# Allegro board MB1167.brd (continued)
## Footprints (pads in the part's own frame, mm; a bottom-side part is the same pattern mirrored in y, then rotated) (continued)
CLM-120-02-L-D
  rect 0.61x1.499 smd: 1(-9.5,-1.57) 2(-9.5,1.57) 3(-8.5,-1.57) 4(-8.5,1.57) 5(-7.5,-1.57) 6(-7.5,1.57) 7(-6.5,-1.57) 8(-6.5,1.57) 9(-5.5,-1.57) 10(-5.5,1.57) 11(-4.5,-1.57) 12(-4.5,1.57) 13(-3.5,-1.57) 14(-3.5,1.57) 15(-2.5,-1.57) 16(-2.5,1.57) 17(-1.5,-1.57) 18(-1.5,1.57) 19(-0.5,-1.57) 20(-0.5,1.57) 21(0.5,-1.57) 22(0.5,1.57) 23(1.5,-1.57) 24(1.5,1.57) 25(2.5,-1.57) 26(2.5,1.57) 27(3.5,-1.57) 28(3.5,1.57) 29(4.5,-1.57) 30(4.5,1.57) 31(5.5,-1.57) 32(5.5,1.57) 33(6.5,-1.57) 34(6.5,1.57) 35(7.5,-1.57) 36(7.5,1.57) 37(8.5,-1.57) 38(8.5,1.57) 39(9.5,-1.57) 40(9.5,1.57)
  round 4.699 hole 3.2: 41(-15.249,0) 42(15.25,0)
CONN_DLR11H0
  round 1.956 hole 1.956 unplated: (-7.14,2.3) (-2.54,-3.7) (2.06,2.3)
  rect 1.219x1.219 hole 0.813: 1(0,0)
  round 1.219 hole 0.813: 2(-2.54,0) 3(-5.08,0)
COUPON
  rect 1.422x1.422 hole 1.016: 1(-3.444,-2.54)
  round 1.422 hole 1.016: 2(-3.444,0) 3(-3.444,2.54) 4(3.447,-2.54) 5(3.447,0) 6(3.447,2.54)
DB9_M
  rect 1.778x2.032 hole 0.965: 1(5.537,0)
  oval 1.778x2.032 hole 0.965: 2(2.769,0) 3(0,0) 4(-2.769,0) 5(-5.537,0) 6(4.166,2.794) 7(1.397,2.794) 8(-1.372,2.794) 9(-4.14,2.794)
  oval 4.572x2.286 hole 3.556x1.27: 10(-12.522,1.397) 11(12.522,1.397)
FBGA64_1_11X13
  round 0.457 smd: A1(-3.5,3.5) A2(-2.5,3.5) A3(-1.5,3.5) A4(-0.5,3.5) A5(0.5,3.5) A6(1.5,3.5) A7(2.5,3.5) A8(3.5,3.5) B1(-3.5,2.5) B2(-2.5,2.5) B3(-1.5,2.5) B4(-0.5,2.5) B5(0.5,2.5) B6(1.5,2.5) B7(2.5,2.5) B8(3.5,2.5) C1(-3.5,1.5) C2(-2.5,1.5) C3(-1.5,1.5) C4(-0.5,1.5) C5(0.5,1.5) C6(1.5,1.5) C7(2.5,1.5) C8(3.5,1.5) D1(-3.5,0.5) D2(-2.5,0.5) D3(-1.5,0.5) D4(-0.5,0.5) D5(0.5,0.5) D6(1.5,0.5) D7(2.5,0.5) D8(3.5,0.5) E1(-3.5,-0.5) E2(-2.5,-0.5) E3(-1.5,-0.5) E4(-0.5,-0.5) E5(0.5,-0.5) E6(1.5,-0.5) E7(2.5,-0.5) E8(3.5,-0.5) F1(-3.5,-1.5) F2(-2.5,-1.5) F3(-1.5,-1.5) F4(-0.5,-1.5) F5(0.5,-1.5) F6(1.5,-1.5) F7(2.5,-1.5) F8(3.5,-1.5) G1(-3.5,-2.5) G2(-2.5,-2.5) G3(-1.5,-2.5) G4(-0.5,-2.5) G5(0.5,-2.5) G6(1.5,-2.5) G7(2.5,-2.5) G8(3.5,-2.5) H1(-3.5,-3.5) H2(-2.5,-3.5) H3(-1.5,-3.5) H4(-0.5,-3.5) H5(0.5,-3.5) H6(1.5,-3.5) H7(2.5,-3.5) H8(3.5,-3.5)
FBGA90_0R8_8X13
  round 0.406 smd: A1(-3.2,5.6) A2(-2.4,5.6) A3(-1.6,5.6) A7(1.6,5.6) A8(2.4,5.6) A9(3.2,5.6) B1(-3.2,4.8) B2(-2.4,4.8) B3(-1.6,4.8) B7(1.6,4.8) B8(2.4,4.8) B9(3.2,4.8) C1(-3.2,4) C2(-2.4,4) C3(-1.6,4) C7(1.6,4) C8(2.4,4) C9(3.2,4) D1(-3.2,3.2) D2(-2.4,3.2) D3(-1.6,3.2) D7(1.6,3.2) D8(2.4,3.2) D9(3.2,3.2) E1(-3.2,2.4) E2(-2.4,2.4) E3(-1.6,2.4) E7(1.6,2.4) E8(2.4,2.4) E9(3.2,2.4) F1(-3.2,1.6) F2(-2.4,1.6) F3(-1.6,1.6) F7(1.6,1.6) F8(2.4,1.6) F9(3.2,1.6) G1(-3.2,0.8) G2(-2.4,0.8) G3(-1.6,0.8) G7(1.6,0.8) G8(2.4,0.8) G9(3.2,0.8) H1(-3.2,0) H2(-2.4,0) H3(-1.6,0) H7(1.6,0) H8(2.4,0) H9(3.2,0) J1(-3.2,-0.8) J2(-2.4,-0.8) J3(-1.6,-0.8) J7(1.6,-0.8) J8(2.4,-0.8) J9(3.2,-0.8) K1(-3.2,-1.6) K2(-2.4,-1.6) K3(-1.6,-1.6) K7(1.6,-1.6) K8(2.4,-1.6) K9(3.2,-1.6) L1(-3.2,-2.4) L2(-2.4,-2.4) L3(-1.6,-2.4) L7(1.6,-2.4) L8(2.4,-2.4) L9(3.2,-2.4) M1(-3.2,-3.2) M2(-2.4,-3.2) M3(-1.6,-3.2) M7(1.6,-3.2) M8(2.4,-3.2) M9(3.2,-3.2) N1(-3.2,-4) N2(-2.4,-4) N3(-1.6,-4) N7(1.6,-4) N8(2.4,-4) N9(3.2,-4) P1(-3.2,-4.8) P2(-2.4,-4.8) P3(-1.6,-4.8) P7(1.6,-4.8) P8(2.4,-4.8) P9(3.2,-4.8) R1(-3.2,-5.6) R2(-2.4,-5.6) R3(-1.6,-5.6) R7(1.6,-5.6) R8(2.4,-5.6) R9(3.2,-5.6)
FTR-120-53-L-D-LC
  round 1.194 hole 1.194 unplated: (-11.43,0) (11.43,0)
  rect 0.711x2.896 smd: 1(-12.065,-2.705) 2(-12.065,2.705) 3(-10.795,-2.705) 4(-10.795,2.705) 5(-9.525,-2.705) 6(-9.525,2.705) 7(-8.255,-2.705) 8(-8.255,2.705) 9(-6.985,-2.705) 10(-6.985,2.705) 11(-5.715,-2.705) 12(-5.715,2.705) 13(-4.445,-2.705) 14(-4.445,2.705) 15(-3.175,-2.705) 16(-3.175,2.705) 17(-1.905,-2.705) 18(-1.905,2.705) 19(-0.635,-2.705) 20(-0.635,2.705) 21(0.635,-2.705) 22(0.635,2.705) 23(1.905,-2.705) 24(1.905,2.705) 25(3.175,-2.705) 26(3.175,2.705) 27(4.445,-2.705) 28(4.445,2.705) 29(5.715,-2.705) 30(5.715,2.705) 31(6.985,-2.705) 32(6.985,2.705) 33(8.255,-2.705) 34(8.255,2.705) 35(9.525,-2.705) 36(9.525,2.705) 37(10.795,-2.705) 38(10.795,2.705) 39(12.065,-2.705) 40(12.065,2.705)
FTR-130-53-L-D-LC
  round 1.194 hole 1.194 unplated: (-17.78,0) (17.78,0)
  rect 0.711x2.896 smd: 1(-18.415,-2.705) 2(-18.415,2.705) 3(-17.145,-2.705) 4(-17.145,2.705) 5(-15.875,-2.705) 6(-15.875,2.705) 7(-14.605,-2.705) 8(-14.605,2.705) 9(-13.335,-2.705) 10(-13.335,2.705) 11(-12.065,-2.705) 12(-12.065,2.705) 13(-10.795,-2.705) 14(-10.795,2.705) 15(-9.525,-2.705) 16(-9.525,2.705) 17(-8.255,-2.705) 18(-8.255,2.705) 19(-6.985,-2.705) 20(-6.985,2.705) 21(-5.715,-2.705) 22(-5.715,2.705) 23(-4.445,-2.705) 24(-4.445,2.705) 25(-3.175,-2.705) 26(-3.175,2.705) 27(-1.905,-2.705) 28(-1.905,2.705) 29(-0.635,-2.705) 30(-0.635,2.705) 31(0.635,-2.705) 32(0.635,2.705) 33(1.905,-2.705) 34(1.905,2.705) 35(3.175,-2.705) 36(3.175,2.705) 37(4.445,-2.705) 38(4.445,2.705) 39(5.715,-2.705) 40(5.715,2.705) 41(6.985,-2.705) 42(6.985,2.705) 43(8.255,-2.705) 44(8.255,2.705) 45(9.525,-2.705) 46(9.525,2.705) 47(10.795,-2.705) 48(10.795,2.705) 49(12.065,-2.705) 50(12.065,2.705) 51(13.335,-2.705) 52(13.335,2.705) 53(14.605,-2.705) 54(14.605,2.705) 55(15.875,-2.705) 56(15.875,2.705) 57(17.145,-2.705) 58(17.145,2.705) 59(18.415,-2.705) 60(18.415,2.705)
FTSH-110-01-L-DV
  round 0.965 hole 0.965 unplated: (-5.08,0) (5.08,0)
  rect 0.737x2.794 smd: 1(-5.715,-2.03) 2(-5.715,2.03) 3(-4.445,-2.03) 4(-4.445,2.03) 5(-3.175,-2.03) 6(-3.175,2.03) 7(-1.905,-2.03) 8(-1.905,2.03) 9(-0.635,-2.03) 10(-0.635,2.03) 11(0.635,-2.03) 12(0.635,2.03) 13(1.905,-2.03) 14(1.905,2.03) 15(3.175,-2.03) 16(3.175,2.03) 17(4.445,-2.03) 18(4.445,2.03) 19(5.715,-2.03) 20(5.715,2.03)
FTSH-125-01-F-DV
  round 0.965 hole 0.965 unplated: (-14.605,0) (14.605,0)
  rect 0.737x2.794 smd: 1(-15.24,-2.03) 2(-15.24,2.03) 3(-13.97,-2.03) 4(-13.97,2.03) 5(-12.7,-2.03) 6(-12.7,2.03) 7(-11.43,-2.03) 8(-11.43,2.03) 9(-10.16,-2.03) 10(-10.16,2.03) 11(-8.89,-2.03) 12(-8.89,2.03) 13(-7.62,-2.03) 14(-7.62,2.03) 15(-6.35,-2.03) 16(-6.35,2.03) 17(-5.08,-2.03) 18(-5.08,2.03) 19(-3.81,-2.03) 20(-3.81,2.03) 21(-2.54,-2.03) 22(-2.54,2.03) 23(-1.27,-2.03) 24(-1.27,2.03) 25(0,-2.03) 26(0,2.03) 27(1.27,-2.03) 28(1.27,2.03) 29(2.54,-2.03) 30(2.54,2.03) 31(3.81,-2.03) 32(3.81,2.03) 33(5.08,-2.03) 34(5.08,2.03) 35(6.35,-2.03) 36(6.35,2.03) 37(7.62,-2.03) 38(7.62,2.03) 39(8.89,-2.03) 40(8.89,2.03) 41(10.16,-2.03) 42(10.16,2.03) 43(11.43,-2.03) 44(11.43,2.03) 45(12.7,-2.03) 46(12.7,2.03) 47(13.97,-2.03) 48(13.97,2.03) 49(15.24,-2.03) 50(15.24,2.03)
HDR_2X3-1_2R54-6
  rect 1.524x1.524 hole 1.016: 1(0,0)
  round 1.524 hole 1.016: 2(0,2.54) 3(2.54,0) 4(2.54,2.54) 5(5.08,0)
HDR_2X6_2R54
  rect 1.524x1.524 hole 1.016: 1(0,0)
  round 1.524 hole 1.016: 2(0,2.54) 3(2.54,0) 4(2.54,2.54) 5(5.08,0) 6(5.08,2.54) 7(7.62,0) 8(7.62,2.54) 9(10.16,0) 10(10.16,2.54) 11(12.7,0) 12(12.7,2.54)
HOLE_C9D4R5
  round 8.992 hole 4.496: 1(0,0)
IDC20S
  round 1.524 hole 1.016: 1(0,0) 2(2.54,0) 3(0,-2.54) 4(2.54,-2.54) 5(0,-5.08) 6(2.54,-5.08) 7(0,-7.62) 8(2.54,-7.62) 9(0,-10.16) 10(2.54,-10.16) 11(0,-12.7) 12(2.54,-12.7) 13(0,-15.24) 14(2.54,-15.24) 15(0,-17.78) 16(2.54,-17.78) 17(0,-20.32) 18(2.54,-20.32) 19(0,-22.86) 20(2.54,-22.86)
IDC34S
  rect 1.524x1.524 hole 1.016: 1(0,0)
  round 1.524 hole 1.016: 2(2.54,0) 3(0,-2.54) 4(2.54,-2.54) 5(0,-5.08) 6(2.54,-5.08) 7(0,-7.62) 8(2.54,-7.62) 9(0,-10.16) 10(2.54,-10.16) 11(0,-12.7) 12(2.54,-12.7) 13(0,-15.24) 14(2.54,-15.24) 15(0,-17.78) 16(2.54,-17.78) 17(0,-20.32) 18(2.54,-20.32) 19(0,-22.86) 20(2.54,-22.86) 21(0,-25.4) 22(2.54,-25.4) 23(0,-27.94) 24(2.54,-27.94) 25(0,-30.48) 26(2.54,-30.48) 27(0,-33.02) 28(2.54,-33.02) 29(0,-35.56) 30(2.54,-35.56) 31(0,-38.1) 32(2.54,-38.1) 33(0,-40.64) 34(2.54,-40.64)
IR_VISHAY3
  rect 0.711x1.397 smd: 1(3.325,0) 2(2.375,0) 3(1.425,0) 4(0.475,0) 5(-0.475,0) 6(-1.425,0) 7(-2.375,0) 8(-3.325,0)
LED2_3528
  rect 1.118x1.499 smd: 1(-0.75,-1.5) 2(-0.75,1.5) 3(0.75,1.5) 4(0.75,-1.5)
LQFP48_0R5_9X9
  rect 1.346x0.279 smd: 1(-4.35,2.75) 2(-4.35,2.25) 3(-4.35,1.75) 4(-4.35,1.25) 5(-4.35,0.75) 6(-4.35,0.25) 7(-4.35,-0.25) 8(-4.35,-0.75) 9(-4.35,-1.25) 10(-4.35,-1.75) 11(-4.35,-2.25) 12(-4.35,-2.75) 25(4.35,-2.75) 26(4.35,-2.25) 27(4.35,-1.75) 28(4.35,-1.25) 29(4.35,-0.75) 30(4.35,-0.25) 31(4.35,0.25) 32(4.35,0.75) 33(4.35,1.25) 34(4.35,1.75) 35(4.35,2.25) 36(4.35,2.75)
  rect 0.279x1.346 smd: 13(-2.75,-4.35) 14(-2.25,-4.35) 15(-1.75,-4.35) 16(-1.25,-4.35) 17(-0.75,-4.35) 18(-0.25,-4.35) 19(0.25,-4.35) 20(0.75,-4.35) 21(1.25,-4.35) 22(1.75,-4.35) 23(2.25,-4.35) 24(2.75,-4.35) 37(2.75,4.35) 38(2.25,4.35) 39(1.75,4.35) 40(1.25,4.35) 41(0.75,4.35) 42(0.25,4.35) 43(-0.25,4.35) 44(-0.75,4.35) 45(-1.25,4.35) 46(-1.75,4.35) 47(-2.25,4.35) 48(-2.75,4.35)
MOLEX_47590001
  rect 0.406x1.346 smd: 1(1.3,0) 2(0.65,0) 3(0,0) 4(-0.65,0) 5(-1.3,0)
  oval 1.067x1.6 hole 0.762x0.838: 6(2.275,0.325) 7(-2.275,0.325)
  oval 1.397x1.905 hole 0.838x1.499: 8(-4.15,-2.855) 9(4.15,-2.855)
  rect 2.896x2.007 smd: 10(0,-2.675)
MP34DT01TR
  rect 0.508x1.067 smd: 1(-0.425,0.675) 2(-0.425,-0.675) 3(0.425,-0.675) 4(0.425,0.675)
  round 0.152 smd: 5(-0.025,-1.753)
MSD_PJS008_
  round 0.711 hole 0.711 unplated: (0,0) (7.55,0)
  rect 0.813x1.6 smd: 1(1.475,5.8) 2(2.575,5.8) 3(3.675,5.8) 4(4.775,5.8) 5(5.875,5.8) 6(6.975,5.8) 7(8.075,5.8) 8(9.175,5.8)
  rect 0.838x1.6 smd: 9(10.325,5.8)
  rect 1.956x1.905 smd: 10(11.225,-4.4)
  rect 1.524x3.073 smd: 11(11.45,-7.35)
  rect 1.397x3.429 smd: 12(-3.503,-7.357)
  rect 1.6x3.505 smd: 13(-3.4,3.65)
  rect 1.194x3.099 smd: 14(11.6,4.15)
OSC_4SM_7X5
  rect 1.803x2.007 smd: 1(-2.54,-2.1) 2(2.54,-2.1) 3(2.54,2.1) 4(-2.54,2.1)
PB10
  rect 1.524x1.016 smd: 1(-4.5,-2.223) 2(-4.5,2.223) 3(4.5,2.223) 4(4.5,-2.223)
PJ3028B
  round 2.007 hole 2.007 unplated: (0,0) (7,0)
  rect 1.219x2.489 smd: 2(-3.9,-4) 7(-2,4)
  rect 2.007x2.489 smd: 3(-1,-4) 4(0.8,4) 6(8.2,-4)
  rect 2.489x2.007 smd: 5(12.25,0.8)
PWR_JACK_DC10
  rect 2.032x4.216 hole 1.016x3.2: 1(0,0)
  oval 4.216x2.032 hole 3.2x1.016: 2(-3.1,-5)
  oval 2.032x4.216 hole 1.016x3.2: 3(-6.2,0)
QFN32_0R5_5X5
  oval 0.864x0.279 smd: 1(-2.42,1.75) 2(-2.42,1.25) 3(-2.42,0.75) 4(-2.42,0.25) 5(-2.42,-0.25) 6(-2.42,-0.75) 7(-2.42,-1.25) 8(-2.42,-1.75) 17(2.42,-1.75) 18(2.42,-1.25) 19(2.42,-0.75) 20(2.42,-0.25) 21(2.42,0.25) 22(2.42,0.75) 23(2.42,1.25) 24(2.42,1.75)
  oval 0.279x0.864 smd: 9(-1.75,-2.42) 10(-1.25,-2.42) 11(-0.75,-2.42) 12(-0.25,-2.42) 13(0.25,-2.42) 14(0.75,-2.42) 15(1.25,-2.42) 16(1.75,-2.42) 25(1.75,2.42) 26(1.25,2.42) 27(0.75,2.42) 28(0.25,2.42) 29(-0.25,2.42) 30(-0.75,2.42) 31(-1.25,2.42) 32(-1.75,2.42)
  rect 3.429x3.429 smd: 33(0,0)
RJ45_J0011D01BNL
  round 3.175 hole 3.175 unplated: (-10.16,6.35) (1.27,6.35)
  rect 1.422x1.422 hole 1.016: 1(0,0)
  round 1.422 hole 1.016: 2(-1.27,-2.54) 3(-2.54,0) 4(-3.81,-2.54) 5(-5.08,0) 6(-6.35,-2.54) 7(-7.62,0) 8(-8.89,-2.54) 9(1.88,11.25) 10(-0.66,9.73) 11(-8.23,11.25) 12(-10.77,9.73)
  round 2.388 hole 1.626: 13(-12.32,3.3) 14(3.43,3.3)
SB_0603
  round 0.152 smd: 1(-0.762,0) 2(0.762,0)
SIP2
  round 1.524 hole 1.016: 1(0,0) 2(2.54,0)
SIP3
  rect 1.524x1.524 hole 1.016: 1(0,0)
  round 1.524 hole 1.016: 2(2.54,0) 3(5.08,0)
SMA
  rect 2.007x1.676 smd: 1(-1.9,0) 2(1.9,0)
SOD-323
  rect 0.813x0.813 smd: 1(-1.125,0) 2(1.125,0)
SOIC8_1R27_4R9X6
  rect 0.559x1.778 smd: 1(-1.905,-2.624) 2(-0.635,-2.624) 3(0.635,-2.624) 4(1.905,-2.624) 5(1.905,2.624) 6(0.635,2.624) 7(-0.635,2.624) 8(-1.905,2.624)
SOIC16W_1R27_10R3X10R33
  rect 0.584x1.956 smd: 1(-4.445,-4.795) 2(-3.175,-4.795) 3(-1.905,-4.795) 4(-0.635,-4.795) 5(0.635,-4.795) 6(1.905,-4.795) 7(3.175,-4.795) 8(4.445,-4.795) 9(4.445,4.795) 10(3.175,4.795) 11(1.905,4.795) 12(0.635,4.795) 13(-0.635,4.795) 14(-1.905,4.795) 15(-3.175,4.795) 16(-4.445,4.795)
SOT23-5
  rect 0.635x1.143 smd: 1(-0.95,-1.2) 2(0,-1.2) 3(0.95,-1.2) 4(0.95,1.2) 5(-0.95,1.2)
SOT-23
  rect 0.635x1.143 smd: 1(-0.95,-1.1) 2(0.95,-1.1) 3(0,1.1)
SOT-223
  rect 1.016x1.803 smd: 1(-2.3,-3.15) 2(0,-3.15) 3(2.3,-3.15)
  rect 3.302x1.803 smd: 4(0,3.15)
SOT-353
  rect 0.406x1.194 smd: 1(-0.65,-0.9) 2(0,-0.9) 3(0.65,-0.9) 4(0.65,0.9) 5(-0.65,0.9)
SSM-104-L-DH
  round 1.194 hole 1.194 unplated: (-2.54,0) (2.54,0)
  rect 1.016x2.286 smd: 1(3.81,-4.698) 2(3.81,4.698) 3(1.27,-4.698) 4(1.27,4.698) 5(-1.27,-4.698) 6(-1.27,4.698) 7(-3.81,-4.698) 8(-3.81,4.698)
SSOP28_0R65_10R2X7R8
  rect 0.356x1.753 smd: 1(-4.225,-3.55) 2(-3.575,-3.55) 3(-2.925,-3.55) 4(-2.275,-3.55) 5(-1.625,-3.55) 6(-0.975,-3.55) 7(-0.325,-3.55) 8(0.325,-3.55) 9(0.975,-3.55) 10(1.625,-3.55) 11(2.275,-3.55) 12(2.925,-3.55) 13(3.575,-3.55) 14(4.225,-3.55) 15(4.225,3.55) 16(3.575,3.55) 17(2.925,3.55) 18(2.275,3.55) 19(1.625,3.55) 20(0.975,3.55) 21(0.325,3.55) 22(-0.325,3.55) 23(-0.975,3.55) 24(-1.625,3.55) 25(-2.275,3.55) 26(-2.925,3.55) 27(-3.575,3.55) 28(-4.225,3.55)
SW1_3TH_2R54_10X2R5
  rect 1.422x1.422 hole 1.016: 1(0,0)
  round 1.422 hole 1.016: 2(2.54,0) 3(5.08,0)
SW-JOY
  round 0.711 hole 0.711 unplated: (0,1.9)
  round 0.991 hole 0.991 unplated: (0,-1.9)
  rect 1.016x1.778 smd: 1(-3.608,1.7) 3(-3.608,-1.7) 4(3.608,-1.7) 6(3.608,1.7)
  rect 1.016x1.016 smd: 2(-3.608,0) 5(3.608,0)
  rect 0.813x0.914 smd: 7(0,3.55) 8(0,-3.55)
  rect 0.813x0.61 smd: 9(-1.3,4) 10(1.3,-4)
TAN-A
  rect 1.27x1.524 smd: 1(1.397,0) 2(-1.397,0)
TO263-3
  rect 1.372x3.429 smd: 1(-2.54,-5) 2(0,-5) 3(2.54,-5)
  rect 10.414x10.795 smd: 4(0,3.625)
TP
  round 1.524 hole 1.016: 1(0,0)
TYCO_ZEN056V130A24LS
  rect 0.61x2.21 smd: 1(-1.745,0)
  rect 0.61x0.94 smd: 2(1.745,0.635) 3(1.745,-0.635)
unnamed
  round 4.496 hole 4.496 unplated: (0,0)
USB-B
  rect 1.27x1.27 hole 0.762: 1(0,0)
  round 1.27 hole 0.762: 2(-2.489,0) 3(-2.489,-2.032) 4(0,-2.032)
  round 3.175 hole 2.413: 5(-7.391,-4.699) 6(4.801,-4.699)
XTAL1
  round 1.27 hole 0.762: 1(0,0) 2(-5.08,0)
XTAL_2SM_3R2X1R5
  rect 1.295x1.6 smd: 1(-1.15,0) 2(1.15,0)
XTAL_2SM_12R7X4R7
  rect 5.486x1.499 smd: 1(-4.25,0) 2(4.25,0)
XTAL_SOCKET
  round 2.108 hole 1.346: 1(0,0) 2(-5.08,0)

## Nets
+1V8: C61.1 C66.1 C68.1 C86.1 C102.1 C103.2 CN4.1 CN4.2 R25.2 R231.2 R235.2 TP1.1 U19.2 U19.4 U23.D1 U23.D8 U23.G9 X3.4
+2V8: C19.1 C119.1 C120.1 CN4.39 CN4.40 R15.1 R230.2 R234.2 T4.1 T5.1 TP5.1 U2.2 U2.4
+3V3: B2.1 B2.4 C1.1 C3.1 C26.1 C28.1 C29.1 C33.2 C37.2 C45.2 C46.2 C56.1 C57.1 C67.1 C83.1 C84.1 C85.1 C90.1 C96.2 C104.1 C107.1 C127.1 C135.1 C143.1 C144.1 C145.1 C146.1 C147.1 C148.1 C149.1 C150.1 C151.1 C152.1 C153.1 C154.1 C155.1 C156.1 C157.1 C158.1 C159.1 C160.1 C161.1 C162.1 C163.1 C164.1 C165.1 C166.1 C168.2 C170.1 C171.2 C173.2 C176.2 CN1.28 CN2.5 CN5.48 CN6.48 CN9.4 CN9.5 CN11.40 CN12.1 CN15.1 CN15.2 CN16.4 CN20.50 CN28.3 JP2.1 JP9.1 JP17.3 L6.1 LD1.1 LD2.1 LD3.1 LD4.1 R1.1 R2.1 R13.2 R20.2 R74.1 R75.2 R76.2 R77.2 R78.2 R79.2 R81.2 R82.2 R85.1 R89.1 R90.2 R92.2 R96.2 R97.1 R114.1 R116.2 R118.2 R120.1 R122.1 R128.1 R131.2 R133.2 R134.1 R135.2 R136.2 R137.2 R141.2 R143.2 R144.2 R146.2 R155.2 R157.1 R158.1 R160.1 R161.1 R162.1 R165.1 R168.2 R170.1 R176.2 R182.2 R186.1 R188.2 R190.1 R191.1 R194.1 R210.1 R211.1 R212.1 R213.1 R214.1 R218.1 R226.1 R229.1 R282.2 R285.2 RV1.1 SW1.1 T1.2 TP4.1 U1.7 U3.2 U5.22 U5.26 U6.22 U6.32 U6.48 U8.6 U8.16 U8.25 U8.30 U8.31 U9.D8 U9.F1 U9.G5 U13.A7 U13.B2 U13.B7 U13.C9 U13.D9 U13.E1 U13.F9 U13.L1 U13.L7 U13.M9 U13.N9 U13.P2 U13.P7 U13.R7 U14.A6 U14.D6 U14.E1 U18.2 U18.4 U19.3 U20.3 U22.1 U22.24 U22.36 U22.48 U23.B2 U23.C2 U23.D2 U23.E9
+3V3_ST_LINK: C51.2 C53.1 C167.2 C169.2 C172.2 C174.2 CN18.4 JP15.1 R203.2 R289.1 R297.2 T3.3 U16.5 U21.1 U21.9 U21.24 U21.36 U21.48
+5V: C54.1 CN1.25 CN5.60 CN6.60 D15.1 JP13.2 JP13.4 JP13.6 JP13.8 JP13.10 JP13.12 L5.1 R142.2 TP14.1 U2.3 U7.5 U11.5 U18.3
D5V: CN5.49 CN6.49 D7.1 JP13.7
GND: B1.1 B1.4 B3.5 B3.7 B3.8 B3.9 B3.10 BT1.2 C1.2 C2.2 C3.2 C4.2 C5.2 C6.1 C7.1 C8.1 C9.1 C10.1 C11.2 C12.1 C13.1 C14.1 C15.2 C16.1 C17.2 C18.1 C19.2 C20.2 C21.2 C22.2 C23.2 C24.1 C27.1 C29.2 C30.2 C31.1 C32.2 C33.1 C34.2 C35.2 C36.2 C37.1 C38.2 C39.2 C40.2 C41.2 C42.2 C43.2 C44.2 C45.1 C46.1 C47.2 C48.2 C49.1 C50.1 C51.1 C52.1 C53.2 C54.2 C55.1 C56.2 C57.2 C58.2 C59.2 C61.2 C63.1 C65.2 C66.2 C67.2 C68.2 C69.2 C72.1 C73.2 C74.1 C75.2 C78.1 C79.1 C80.2 C81.2 C82.2 C83.2 C84.2 C85.2 C86.2 C87.2 C89.2 C90.2 C91.1 C92.1 C93.1 C94.1 C95.1 C96.1 C97.2 C99.1 C101.2 C102.2 C103.1 C105.2 C106.2 C107.2 C108.2 C109.2 C110.1 C111.2 C112.2 C113.1 C114.2 C115.2 C116.2 C117.2 C118.2 C119.2 C120.2 C121.2 C122.2 C123.2 C124.2 C125.2 C126.2 C128.2 C129.2 C130.2 C131.2 C132.2 C133.2 C134.1 C135.2 C137.1 C138.2 C139.2 C140.2 C141.1 C142.2 C143.2 C144.2 C145.2 C146.2 C147.2 C148.2 C149.2 C150.2 C151.2 C152.2 C153.2 C154.2 C155.2 C156.2 C157.2 C158.2 C159.2 C160.2 C161.2 C162.2 C163.2 C164.2 C165.2 C166.2 C167.1 C168.1 C169.1 C170.2 C171.1 C172.1 C173.1 C174.1 C175.1 C176.1 CN1.2 CN1.4 CN1.6 CN1.8 CN1.10 CN1.12 CN1.16 CN1.18 CN1.20 CN1.22 CN1.24 CN1.30 CN1.32 CN2.7 CN3.2 CN4.3 CN4.4 CN4.7 CN4.8 CN4.11 CN4.12 CN4.16 CN4.21 CN4.22 CN4.37 CN4.38 CN4.41 CN4.42 CN5.1 CN5.10 CN5.19 CN5.30 CN5.39 CN5.50 CN5.59 CN6.1 CN6.10 CN6.19 CN6.30 CN6.39 CN6.50 CN6.59 CN7.5 CN7.10 CN7.11 CN9.8 CN9.13 CN9.14 CN10.9 CN10.10 CN10.29 CN10.30 CN11.9 CN11.10 CN11.29 CN11.30 CN12.3 CN12.5 CN12.9 CN12.11 CN12.13 CN12.15 CN12.17 CN12.19 CN13.5 CN13.6 CN13.7 CN13.8 CN13.9 CN13.10 CN14.5 CN14.6 CN14.7 CN14.8 CN14.9 CN14.10 CN15.4 CN15.6 CN15.8 CN15.10 CN15.12 CN15.14 CN15.16 CN15.18 CN15.20 CN16.6 CN16.9 CN18.2 CN19.2 CN20.1 CN20.2 CN20.19 CN20.20 CN20.30 CN20.34 CN20.37 CN21.4 CN21.5 CN21.6 CN22.3 CN22.6 CN22.10 CN22.11 CN24.2 CN26.3 CN27.2 CN27.5 CN28.2 D3.B1 D3.B2 D4.B1 D4.B2 D5.D2 D6.D2 D14.3 H1.1 H2.1 JP10.1 JP11.1 JP16.1 L1.1 L3.4 L3.5 L3.6 L4.1 LD10.2 LD12.1 R6.2 R12.2 R21.2 R23.1 R32.1 R36.1 R38.1 R40.1 R80.1 R83.1 R94.1 R98.1 R105.1 R110.1 R129.1 R139.1 R140.1 R145.1 R148.1 R149.1 R153.1 R163.2 R172.2 R173.1 R174.1 R175.2 R178.2 R179.2 R181.1 R184.1 R185.1 R187.1 R197.2 R208.2 R217.2 R219.1 R221.2 R222.2 R223.1 R249.1 R292.1 R296.1 RV1.3 SB64.1 SW1.3 T2.2 T6.2 T7.2 TP2.1 TP3.1 TP13.1 TP16.1 U1.5 U1.8 U3.10 U4.F2 U4.F6 U4.F7 U4.F8 U4.F9 U4.F10 U4.G6 U4.G10 U4.H6 U4.H10 U4.J6 U4.J10 U4.K6 U4.K7 U4.K8 U4.K9 U4.K10 U4.L6 U4.M1 U4.N1 U5.23 U5.25 U6.15 U6.19 U6.35 U6.36 U6.47 U7.2 U8.1 U8.2 U8.33 U9.E8 U9.H2 U9.H7 U10.2 U11.2 U12.2 U13.A3 U13.B3 U13.B8 U13.C1 U13.D1 U13.E9 U13.F1 U13.L3 U13.L9 U13.M1 U13.N1 U13.P3 U13.P8 U13.R3 U14.D1 U14.E6 U15.2 U16.2 U17.4 U18.1 U19.1 U20.2 U21.8 U21.23 U21.35 U21.47 U22.8 U22.23 U22.35 U22.47 U23.A1 U23.A3 U23.A4 U23.A5 U23.C1 U23.D6 U23.E2 U23.E7 U23.E8 U23.F7 U23.G5 U23.H9 U24.5 U25.2 U25.5 X3.2
VBUS_FS1: C48.1 CN6.54 CN13.1 D5.B3 D9.1 JP13.3 R108.1 R261.2 U11.1
VBUS_FS2: CN14.1 D6.B3 D10.1 JP13.5 R138.1 R259.1 SB13.1
VBUS_HS: CN8.1 D3.A1 D8.1 JP13.1 L2.2
VDD_MCU: C26.2 C28.2 C104.2 C106.1 C108.1 C109.1 C112.1 C114.1 C115.1 C116.1 C117.1 C118.1 C121.1 C122.1 C123.1 C124.1 C125.1 C126.1 C127.2 C128.1 C129.1 C130.1 C131.1 C132.1 C133.1 JP2.2 L7.1 U4.E7 U4.E8 U4.E9 U4.E10 U4.F4 U4.F5 U4.F11 U4.G5 U4.G11 U4.H5 U4.H11 U4.J5 U4.J11 U4.K5 U4.K11 U4.L7 U4.L8 U4.L9 U4.L10
VDDA: C111.1 C113.2 L7.2 R33.1 TP9.1 U4.R1
A0: CN11.14 R242.2 U9.E2 U13.G8 U14.A3
A1: CN11.12 R240.2 U9.D2 U13.G9 U14.A4
A2: CN11.8 R239.2 U9.C2 U13.F7 U14.A5
A3: CN11.5 R236.2 U9.A2 U13.F3 U14.B3
A4: CN11.3 R233.2 U9.B2 U13.G1 U14.B4
A5: CN11.1 R232.2 U9.D3 U13.G2 U14.C3
A6: CN10.5 R255.2 U9.C3 U13.G3 U14.C4
A7: CN10.3 R253.2 U9.A3 U13.H1 U14.D4
A8: CN10.4 R256.2 U9.B6 U13.H2 U14.H2
A9: CN10.18 R266.2 U9.A6 U13.J3 U14.H3
A10: CN10.6 R258.2 U9.C6 U13.G7 U14.H4
A11: CN10.7 R257.2 U9.D6 U13.H9 U14.H5
A12: CN10.33 R272.2 U9.B7 U14.G3
A13: CN10.34 R262.2 U9.A7 U14.G4
A14: CN10.28 R273.2 U9.C7 U13.J7 U14.F3
A15: CN10.25 R264.2 U9.D7 U13.H8 U14.F4
A16: CN10.21 R265.1 U9.E7 U14.E4
A17: CN10.23 R274.2 U9.B3 U14.D3
A18: CN10.31 R263.2 U9.C4 U14.H1
A19: CN11.13 R37.2 R38.2 U9.D5 U14.G2
A20: CN11.11 R35.2 R36.2 U9.D4 U14.H6
A21: CN11.4 R23.2 R31.2 U9.C5
A22: CN11.7 R32.2 R34.2 U9.B8
A23: CN11.16 R39.2 R40.2 U9.C8
AIN_1: R186.2 R187.2 U21.10
BOOT0: JP1.2 R4.1 U4.E6
CAMERA_CLK: CN4.20 X3.3
CUR_SEL: R150.1 U21.22
D0: CN10.39 R72.2 U9.E3 U13.R8 U14.B6
D1: CN10.38 R60.2 U9.H3 U13.N7 U14.C5
D2: CN11.31 R267.2 U9.E4 U13.R9 U14.C6
D3: CN11.32 R276.2 U9.H4 U13.N8 U14.D5
D4: CN10.11 R63.2 U9.H5 U13.P9 U14.E5
D5: CN10.14 R53.2 U9.E5 U13.M8 U14.F5
D6: CN10.12 R52.2 U9.H6 U13.M7 U14.F6
D7: CN10.13 R64.2 U9.E6 U13.L8 U14.G6
D8: CN10.16 R54.2 U9.F3 U13.L2 U14.B1
D9: CN10.15 R65.2 U9.G3 U13.M3 U14.C1
D10: CN10.19 R67.2 U9.F4 U13.M2 U14.C2
D11: CN10.20 R55.2 U9.G4 U13.P1 U14.D2
D12: CN10.17 R66.2 U9.F5 U13.N2 U14.E2
D13: CN10.35 R59.2 U9.G6 U13.R1 U14.F2
D14: CN10.37 R70.2 U9.F6 U13.N3 U14.F1
D15: CN10.36 R71.2 U9.G7 U13.R2 U14.G1
D16: CN10.22 R56.1 U13.E8
D17: CN10.26 R57.1 U13.D7
D18: CN10.24 R68.1 U13.D8
D19: CN10.27 R69.1 U13.B9
D20: CN10.32 R58.1 U13.C8
D21: CN11.39 R271.1 U13.A9
D22: CN11.38 R279.1 U13.C7
D23: CN11.36 R278.1 U13.A8
D24: CN11.37 R270.1 U13.A2
D25: CN11.35 R269.1 U13.C3
D26: CN11.33 R268.1 U13.A1
D27: CN11.34 R277.1 U13.C2
D28: CN11.22 R250.1 U13.B1
D29: CN11.18 R245.1 U13.D2
D30: CN11.20 R246.1 U13.D3
D31: CN11.21 R248.1 U13.E2
E5V: C58.1 D11.1 JP13.9 L3.3
I2C1_SCL_C: CN4.13 R183.2 R230.1 T4.2
I2C1_SDA_C: CN4.14 R234.1 R298.2 T5.2
LCD_B0: CN6.27 CN20.21 U4.B10
LCD_B1: CN6.26 CN20.23 U4.B9
LCD_B2: CN6.20 CN20.25 U4.C9
LCD_B3: CN6.22 CN20.27 U4.D10
LCD_B4: CN6.16 CN20.29 U4.D8
LCD_B5: CN6.13 CN20.31 U4.D7
LCD_B6: CN6.12 CN20.33 U4.C6
LCD_B7: CN6.11 CN20.35 U4.C5
LCD_G0: CN5.53 CN20.4 U4.J12
LCD_G1: CN5.57 CN20.6 U4.H12
LCD_G2: CN5.45 CN20.8 U4.J13
LCD_G3: CN5.55 CN20.10 U4.H13
LCD_G4: CN6.35 CN20.12 U4.G12
LCD_G5: CN6.37 CN20.14 U4.G13
LCD_G6: CN6.34 CN20.16 U4.F12
LCD_G7: CN6.38 CN20.18 U4.F13
LCD_R0: CN6.5 CN20.3 U4.G4
LCD_R1: CN5.54 CN20.5 U4.R6
LCD_R2: CN5.58 CN20.7 U4.R7
LCD_R3: CN5.56 CN20.9 U4.P7
LCD_R4: CN5.31 CN20.11 U4.N8
LCD_R5: CN5.34 CN20.13 U4.M9
LCD_R6: CN5.42 CN20.15 U4.M14
LCD_R7: CN5.44 CN20.17 U4.K12
LED_STLINK: R201.1 R202.1 U21.30
LOOP: TP15.1 U22.14
MCO: U21.29
MFX_SWCLK: CN19.3 U22.37
MFX_SWDIO: CN19.1 U22.34
MIC_CLK: CN24.3 CN27.3 JP19.2 SB20.1
MIC_DATA: CN24.1 CN27.1 JP18.2 SB21.2
MIC_VDD: C89.1 C101.1 CN24.4 CN27.4 JP17.2 R198.2 R199.2 U24.1 U25.1
NETB2_2: B2.2 B2.3 C100.2 R216.1 R217.1
NETB3_1: B3.1 C93.2 R212.2 U22.20
NETB3_2: B3.2 C92.2 R211.2 U22.18
NETB3_3: B3.3 C91.2 R210.2 U22.19
NETB3_4: B3.4 C95.2 R214.2 U22.39
NETB3_6: B3.6 C94.2 R213.2 U22.40
NETBT1_1: BT1.1 JP9.3
NETC2_1: C2.1 C4.1 R1.2 U1.6
NETC5_1: C5.1 R6.1 R15.2 U2.1
NETC6_2: C6.2 CN1.31 SB2.2 SB34.1
NETC7_2: C7.2 CN1.27 SB1.2 SB48.1
NETC8_2: C8.2 CN1.33 SB23.1
NETC9_2: C9.2 CN1.34 SB30.1
NETC10_2: C10.2 CN1.29 SB50.1
NETC11_1: C11.1 R7.2 SB53.2
NETC12_2: C12.2 R8.1 SB44.2
NETC13_2: C13.2 R9.1 SB38.2
NETC14_2: C14.2 R10.1 SB31.2
NETC15_1: C15.1 R11.2 R12.1 SB40.2
NETC16_2: C16.2 CN1.1 R13.1 R14.1
NETC17_1: C17.1 SB2.1
NETC18_2: C18.2 SB1.1 SB56.1
NETC20_1: C20.1 R19.2 X1.2
NETC21_1: C21.1 R17.1 X2.1
NETC22_1: C22.1 R18.1 X2.2
NETC24_2: C24.2 R29.1 R30.1
NETC25_1: C25.1 U5.1
NETC25_2: C25.2 U5.2
NETC27_2: C27.2 U5.3
NETC30_1: C30.1 JP6.1 X4.1
NETC31_2: C31.2 R73.2 X4.2
NETC32_1: C32.1 U4.E11
NETC34_1: C34.1 C35.1 C43.1 C44.1 CN8.5 CN8.6 CN8.7 CN8.8 CN8.9 CN8.10 L1.2
NETC36_1: C36.1 SB12.1 SB13.2 U7.1
NETC38_1: C38.1 R87.2 U8.28 X5.1
NETC39_1: C39.1 R87.1 U8.27 X5.2
NETC40_1: C40.1 R85.2 U9.B5
NETC41_1: C41.1 C142.1 U8.29
NETC42_1: C42.1 C47.1 U8.15 U8.26
NETC49_2: C49.2 U16.4
NETC50_2: C50.2 C52.2 D7.2 D8.2 D9.2 D10.2 D11.2 D12.2 U16.1 U16.3
NETC60_1: C60.1 D13.3 L3.1 Z1.2
NETC60_2: C60.2 CN17.2 CN17.3 D13.2 L3.2 Z1.1
NETC62_1: C62.1 C70.1 CN20.45 L5.2
NETC62_2: C62.2 C70.2 CN20.47 CN20.49 L4.2
NETC63_2: C63.2 U23.C9
NETC64_1: C64.1 U23.D7
NETC64_2: C64.2 CN26.2 R177.1 R223.2
NETC65_1: C65.1 U23.D9
NETC69_1: C69.1 U23.E6
NETC71_1: C71.1 U23.H8
NETC71_2: C71.2 U23.G8
NETC72_2: C72.2 JP17.1 U23.A7
NETC73_1: C73.1 U23.G7
NETC74_2: C74.2 R177.2 U23.B6
NETC75_1: C75.1 U23.H7
NETC76_1: C76.1 CN26.4 U23.G6
NETC76_2: C76.2 R178.1
NETC77_1: C77.1 CN26.6 U23.H6
NETC77_2: C77.2 R179.1
NETC78_2: C78.2 C82.1 L6.2 U22.9
NETC79_2: C79.2 D16.1 R182.1 U22.7
NETC87_1: C87.1 U23.F1
NETC88_1: C88.1 R196.1 R197.1
NETC88_2: C88.2 U23.A2
NETC97_1: C97.1 CN28.1 R215.2
NETC98_1: C98.1 R219.2 R220.2
NETC98_2: C98.2 U23.B3
NETC100_1: C100.1 R218.2
NETC134_2: C134.2 U5.27
NETC136_1: C136.1 U5.24
NETC136_2: C136.2 U5.28
NETC137_2: C137.2 C139.1 C140.1 C141.2 U6.18 U6.23 U6.37
NETC138_1: C138.1 U4.L11
NETCN1_3: CN1.3 SB62.2
NETCN1_5: CN1.5 SB35.1
NETCN1_9: CN1.9 SB59.1
NETCN1_11: CN1.11 SB58.2
NETCN1_13: CN1.13 SB39.1
NETCN1_14: CN1.14 R11.1
NETCN1_15: CN1.15 R10.2
NETCN1_17: CN1.17 R9.2
NETCN1_19: CN1.19 R8.2
NETCN1_21: CN1.21 SB46.2
NETCN1_23: CN1.23 SB42.2
NETCN1_26: CN1.26 R7.1
NETCN2_1: CN2.1 R3.2
NETCN2_3: CN2.3 R5.2
NETCN2_4: CN2.4 R16.1
NETCN3_1: CN3.1 R28.1 R29.2
NETCN4_15: CN4.15 R229.2 U22.33
NETCN4_17: CN4.17 R231.1 U22.32
NETCN4_18: CN4.18 TP7.1
NETCN4_19: CN4.19 R235.1 U22.31
NETCN4_32: CN4.32 JP23.1 R301.1
NETCN4_33: CN4.33 SB5.1
NETCN4_34: CN4.34 TP8.1
NETCN4_35: CN4.35 TP11.1
NETCN4_36: CN4.36 TP10.1
NETCN5_3: CN5.3 SB27.2
NETCN5_5: CN5.5 R224.2
NETCN5_6: CN5.6 SB28.2
NETCN6_3: CN6.3 SB26.2
NETCN6_4: CN6.4 SB25.2
NETCN7_2: CN7.2 U5.6
NETCN7_3: CN7.3 U5.10
NETCN7_6: CN7.6 U5.5
NETCN7_8: CN7.8 U5.7
NETCN8_2: CN8.2 D4.A1 U8.8
NETCN8_3: CN8.3 D4.A2 U8.7
NETCN8_4: CN8.4 D3.A2 U8.5
NETCN9_1: CN9.1 R120.2 U6.17
NETCN9_2: CN9.2 R114.2 U6.16
NETCN9_3: CN9.3 R89.2 U6.14
NETCN9_6: CN9.6 R97.2 U6.13
NETCN9_9: CN9.9 R131.1
NETCN9_10: CN9.10 R76.1 U6.28
NETCN9_11: CN9.11 R79.1 U6.26
NETCN9_12: CN9.12 R78.1
NETCN11_6: CN11.6 JP5.1 R92.1 U9.A4
NETCN12_2: CN12.2 CN15.7 R86.1 R141.1 U15.1
NETCN12_4: CN12.4 CN15.9 R93.1 R140.2 U15.3
NETCN12_6: CN12.6 CN15.13 R99.1 R111.2 R143.1 U15.4
NETCN12_8: CN12.8 CN15.5 R101.1 R136.1 U12.5
NETCN12_10: CN12.10 CN15.15 R104.1 U15.5
NETCN12_12: CN12.12 SB7.1 U12.1
NETCN12_14: CN12.14 R111.1 SB8.1 U10.5
NETCN12_16: CN12.16 R113.1 SB6.1 U10.4
NETCN12_18: CN12.18 SB3.1 U10.3
NETCN12_20: CN12.20 SB17.1 U10.1
NETCN13_2: CN13.2 D5.D1 R284.1
NETCN13_3: CN13.3 D5.C1 R283.1
NETCN13_4: CN13.4 D5.A3 R117.1
NETCN14_2: CN14.2 D6.D1 R288.1
NETCN14_3: CN14.3 D6.C1 R286.1
NETCN14_4: CN14.4 D6.A3 SB51.1
NETCN15_3: CN15.3 R112.1 R113.2 R137.1 U12.4
NETCN15_11: CN15.11 R144.1 R145.2
NETCN15_17: CN15.17 R148.2
NETCN15_19: CN15.19 R149.2
NETCN16_1: CN16.1 R162.2 R281.1
NETCN16_2: CN16.2 R161.2 R275.1
NETCN16_3: CN16.3 R160.2 SB63.1
NETCN16_7: CN16.7 R158.2 SB61.2
NETCN16_8: CN16.8 R157.2 R260.1
NETCN16_10: CN16.10 R154.2
NETCN17_1: CN17.1 D13.1
NETCN19_4: CN19.4 R165.2
NETCN20_22: CN20.22 R192.1
NETCN20_39: CN20.39 U22.27
NETCN20_43: CN20.43 SB60.1
NETCN21_2: CN21.2 R166.1
NETCN21_3: CN21.3 R169.1 R171.1
NETCN22_2: CN22.2 D14.1 JP12.2 U20.6
NETCN22_5: CN22.5 R174.2
NETCN22_7: CN22.7 D14.2 R164.1 U20.7
NETCN22_9: CN22.9 R170.2
NETCN24_5: CN24.5 R198.1
NETCN25_2: CN25.2 R222.1
NETCN25_3: CN25.3 R221.1
NETCN25_4: CN25.4 R220.1
NETCN25_6: CN25.6 R196.2
NETD1_1: D1.1 U5.20
NETD1_2: D1.2 JP1.1
NETD2_2: D2.2 JP3.1
NETD5_C3: D5.C3 R283.2 SB52.1
NETD15_2: D15.2 R209.1
NETJP3_2: JP3.2 U5.16
NETJP5_3: JP5.3 JP18.3
NETJP6_2: JP6.2 U6.34
NETJP6_3: JP6.3 SB57.1
NETJP7_1: JP7.1 U5.17
NETJP7_2: JP7.2 JP14.1
NETJP7_3: JP7.3 U1.4
NETJP8_2: JP8.2 U20.4
NETJP9_2: JP9.2 U4.C1
NETJP10_2: JP10.2 R116.1 U9.B4
NETJP11_2: JP11.2 R163.1 U20.8
NETJP11_3: JP11.3 R168.1
NETJP12_1: JP12.1 R164.2
NETJP15_2: JP15.2 R208.1 R209.2 U21.39
NETJP16_2: JP16.2 R289.2 U21.21
NETJP18_1: JP18.1 U23.A9
NETJP19_1: JP19.1 U23.C6
NETJP19_3: JP19.3 R280.2
NETJP20_1: JP20.1 U1.3 U5.13
NETJP20_2: JP20.2 SB54.1
NETJP21_1: JP21.1 U23.G1
NETJP21_2: JP21.2 SB24.1
NETJP21_3: JP21.3 R75.1 SB11.2 U6.30
NETJP22_1: JP22.1 U23.F2
NETJP22_2: JP22.2 SB22.2
NETJP22_3: JP22.3 SB10.2 U6.31
NETJP23_3: JP23.3 R300.1
NETJP24_1: JP24.1 R30.2 R302.1
NETJP24_3: JP24.3 R299.1
NETL2_1: L2.1 R84.2 R103.2 SB12.2
NETLD1_2: LD1.2 R207.2 R299.2
NETLD2_2: LD2.2 R206.2
NETLD3_2: LD3.2 R205.2 R300.2
NETLD4_2: LD4.2 R204.2
NETLD5_1: LD5.1 R96.1
NETLD5_2: LD5.2 T6.3
NETLD6_1: LD6.1 R282.1
NETLD6_2: LD6.2 R121.2 R122.2 U7.3 U8.10
NETLD7_1: LD7.1 R118.1
NETLD7_2: LD7.2 T7.3
NETLD8_1: LD8.1 R133.1
NETLD8_2: LD8.2 R132.2 R134.2 U11.3
NETLD9_1: LD9.1 R135.1
NETLD9_2: LD9.2 T2.3
NETLD10_1: LD10.1 R142.1
NETLD11_1: LD11.1 R200.2
NETLD11_2: LD11.2 R156.2 U17.8
NETLD12_2: LD12.2 R201.2
NETLD12_3: LD12.3 R202.2
NETLD12_4: LD12.4 R203.1
NETR2_2: R2.2 U1.1
NETR4_2: R4.2 SW1.2
NETR20_1: R20.1 R21.1 U4.E5
NETR22_1: R22.1 U4.K1
NETR24_1: R24.1 U4.K2
NETR25_1: R25.1 X3.1
NETR26_1: R26.1 U4.L2
NETR27_1: R27.1 R28.2
NETR27_2: R27.2 RV1.2
NETR31_1: R31.1 SB3.2 SB4.2 U4.B1
NETR34_1: R34.1 SB16.2 SB17.2 SB18.2 U4.B2
NETR35_1: R35.1 SB6.2 U4.A1
NETR37_1: R37.1 SB8.2 U4.A2
NETR39_1: R39.1 R247.2 SB7.2 U4.A3
NETR41_1: R41.1 U4.L3
NETR42_1: R42.1 U4.M5
NETR43_1: R43.1 U4.B6
NETR44_1: R44.1 U4.B7
NETR45_1: R45.1 U6.46
NETR46_1: R46.1 U6.45
NETR46_2: R46.2 SB45.2
NETR47_1: R47.1 U6.44
NETR47_2: R47.2 SB55.2
NETR48_1: R48.1 U6.43
NETR48_2: R48.2 SB43.2
NETR49_1: R49.1 U6.39
NETR49_2: R49.2 SB37.1
NETR50_1: R50.1 U6.38
NETR50_2: R50.2 SB29.1
NETR51_1: R51.1 U4.P8
NETR52_1: R52.1 U4.P9
NETR53_1: R53.1 U4.N9
NETR54_1: R54.1 U4.P10
NETR55_1: R55.1 U4.P11
NETR56_2: R56.2 U4.P14
NETR57_2: R57.2 U4.N14
NETR58_2: R58.2 U4.M15
NETR59_1: R59.1 U4.L15
NETR60_1: R60.1 U4.K13
NETR61_1: R61.1 U4.H14
NETR62_1: R62.1 U6.1
NETR62_2: R62.2 SB41.2
NETR63_1: R63.1 U4.R8
NETR64_1: R64.1 U4.R9
NETR65_1: R65.1 U4.R10
NETR66_1: R66.1 U4.R11
NETR67_1: R67.1 U4.R12
NETR68_2: R68.2 U4.P15
NETR69_2: R69.2 U4.N15
NETR70_1: R70.1 U4.L14
NETR71_1: R71.1 U4.K15
NETR72_1: R72.1 U4.L12
NETR73_1: R73.1 U6.33
NETR74_2: R74.2 U6.7 U22.26
NETR77_1: R77.1 U6.27
NETR80_2: R80.2 R84.1 T6.1
NETR81_1: R81.1 U6.20
NETR82_1: R82.1 U6.21
NETR83_2: R83.2 U6.24
NETR88_1: R88.1 U8.24
NETR90_1: R90.1 R91.1 U9.F2
NETR94_2: R94.2 SB14.2 SB15.2 U7.4
NETR95_1: R95.1 U8.23
NETR98_2: R98.2 U8.32
NETR100_1: R100.1 U8.22
NETR102_1: R102.1 U8.21
NETR103_1: R103.1 U8.4
NETR105_2: R105.2 R108.2 T7.1
NETR106_1: R106.1 U8.20
NETR107_1: R107.1 U9.A5 U14.G5
NETR109_1: R109.1 U8.19
NETR110_2: R110.2 T1.3 U8.9
NETR115_1: R115.1 U8.18
NETR119_1: R119.1 U8.17
NETR121_1: R121.1 U22.29
NETR123_1: R123.1 U8.11
NETR124_1: R124.1 U8.12
NETR125_1: R125.1 U8.13
NETR126_1: R126.1 U8.14
NETR127_1: R127.1 R128.2 T1.1
NETR129_2: R129.2 R130.1 U11.4
NETR130_2: R130.2 U22.17
NETR132_1: R132.1 U22.16
NETR138_2: R138.2 R139.2 T2.1
NETR146_1: R146.1 R147.1 U14.B5
NETR150_2: R150.2 R151.1
NETR151_2: R151.2 R152.2 U17.5
NETR152_1: R152.1 R153.2
NETR154_1: R154.1 R155.1 U22.28
NETR167_1: R167.1 U22.21
NETR167_2: R167.2 U22.22
NETR171_2: R171.2 T3.2
NETR172_1: R172.1 U22.44
NETR173_2: R173.2 U21.44
NETR175_1: R175.1 R176.1 U22.45
NETR180_1: R180.1 R181.2 U22.2
NETR184_2: R184.2 U21.2
NETR185_2: R185.2 U21.3
NETR188_1: R188.1 U23.D4 U23.D5
NETR189_2: R189.2 U23.F3
NETR193_1: R193.1 U23.E3
NETR194_2: R194.2 U23.G2
NETR195_2: R195.2 U23.H1
NETR199_1: R199.1 U24.2
NETR204_1: R204.1 U22.13
NETR205_1: R205.1 U22.12
NETR206_1: R206.1 U22.11
NETR207_1: R207.1 U22.10
NETR225_2: R225.2 U4.H3
NETR227_1: R227.1 U3.8
NETR228_2: R228.2 U3.9
NETR232_1: R232.1 U4.K3
NETR233_1: R233.1 U4.J2
NETR236_1: R236.1 U4.H2
NETR237_1: R237.1 U3.1
NETR238_2: R238.2 U3.15
NETR239_1: R239.1 U4.G2
NETR240_1: R240.1 U4.E2
NETR241_2: R241.2 U6.5
NETR242_1: R242.1 U4.D2
NETR243_2: R243.2 U6.3
NETR244_2: R244.2 U6.4
NETR245_2: R245.2 U4.D4
NETR246_2: R246.2 U4.E4
NETR247_1: R247.1 U6.6
NETR248_2: R248.2 SB9.1 U4.D5
NETR249_2: R249.2 U4.L5
NETR250_2: R250.2 U4.D6
NETR251_2: R251.2 SB47.1 U4.J4
NETR252_2: R252.2 U6.2
NETR253_1: R253.1 U4.N6
NETR254_2: R254.2 U4.J3
NETR255_1: R255.1 U4.M6
NETR256_1: R256.1 U4.P6
NETR257_1: R257.1 U4.M7
NETR258_1: R258.1 U4.N7
NETR262_1: R262.1 U4.M12
NETR263_1: R263.1 U4.M11
NETR264_1: R264.1 U4.N11
NETR265_2: R265.2 U4.N10
NETR266_1: R266.1 U4.M8
NETR267_1: R267.1 U4.B12
NETR268_2: R268.2 U4.C14
NETR269_2: R269.2 U4.D14
NETR270_2: R270.2 U4.E14
NETR271_2: R271.2 U4.E12
NETR272_1: R272.1 U4.M13
NETR273_1: R273.1 U4.N12
NETR274_1: R274.1 U4.M10
NETR276_1: R276.1 U4.C12
NETR277_2: R277.2 U4.C13
NETR278_2: R278.2 U4.D13
NETR279_2: R279.2 U4.E13
NETR285_1: R285.1 U9.F7
NETR287_1: R287.1 U13.J2
NETR290_2: R290.2 U22.42
NETR291_2: R291.2 U22.43
NETR292_2: R292.2 U21.20
NETR293_1: R293.1 R294.1 R296.2 T3.1
NETR295_2: R295.2 U22.46
NETSB9_2: SB9.2 U6.41
NETSB14_1: SB14.1 U22.30
NETSB15_1: SB15.1 U8.3
NETSB18_1: SB18.1 U23.D3
NETSB20_2: SB20.2 U24.3 U25.3
NETSB21_1: SB21.1 U24.4 U25.4
NETSB32_1: SB32.1 U23.E4
NETSB36_1: SB36.1 U6.40
NETSB47_2: SB47.2 U6.42
NETSB49_1: SB49.1 U20.1
NETTP12_1: TP12.1 U6.25
NETU22_15: U22.15 U23.G3
OSC_IN: C80.1 U21.5 X6.2
OSC_OUT: C81.1 U21.6 X6.1
PA0: CN5.15 SB32.2 SB34.2 SB36.2 U4.N3
PA1: CN5.14 SB23.2 SB29.2 U4.N2
PA2: CN5.13 SB24.2 SB30.2 U4.P2
PA3: CN5.18 R88.2 U4.R2
PA4: CN4.31 CN5.21 U4.N4
PA5: CN5.24 R126.2 U4.P4
PA6: CN5.20 R14.2 SB5.2 U4.P3
PA7: CN5.22 SB35.2 SB37.2 U4.R3
PA8: CN6.52 SB56.2 SB57.2 SB60.2 U4.F15
PA9: CN6.43 R261.1 SB54.2 U4.E15
PA10: CN6.44 JP14.2 R117.2 U4.D15
PA11: CN6.41 D5.D3 JP8.1 R284.2 SB50.2 U4.C15
PA12: CN6.42 SB48.2 SB49.2 SB52.2 U4.B15
PA13: CN6.40 R86.2 U4.A15 U21.25 U21.27
PA14: CN6.36 R93.2 U4.A14 U21.15 U21.26
PA15: CN6.32 R101.2 U4.A13 U21.17
PAR_D0: CN4.23 CN6.58 JP4.3 SB62.1 U4.H15
PAR_D1: CN1.7 CN4.24 CN6.56 R280.1 U4.G15
PAR_D2: CN4.25 CN6.51 SB58.1 SB61.1 U4.G14
PAR_D3: CN4.26 CN6.46 R260.2 U4.F14
PAR_D4: CN4.27 CN6.53 R275.2 U4.B13
PAR_D5: CN4.28 CN6.23 U4.C11
PAR_D6: CN4.29 SB4.1
PAR_D7: CN4.30 SB16.1
PAR_D8: CN4.9 CN6.55 R16.2 R281.2 U4.B14
PAR_D9: CN4.10 CN6.28 CN16.5 U4.A12
PAR_D10: CN4.5 CN6.47 JP5.2 U4.B11
PAR_D11: CN4.6 CN6.57 SB63.2 U4.D12
PB0: CN5.52 R95.2 SB59.2 U4.R5
PB1: CN5.26 R100.2 SB39.2 U4.R4
PB2: CN5.29 R42.2 U3.16
PB3: CN6.45 JP4.2 U4.A10
PB4: CN6.24 R112.2 U4.A9 U21.19
PB5: CN5.4 R119.2 U4.A8
PB6: CN6.18 R43.2 R226.2 U3.7
PB7: CN6.21 JP23.2 R301.2 U4.B5
PB8: CN6.31 CN20.40 R5.1 R183.1 R190.2 R195.1 R290.1 T4.3 U4.A7
PB9: CN6.14 CN20.38 R3.1 R189.1 R191.2 R291.1 R298.1 T5.3 U4.B4
PB10: CN5.33 R102.2 U4.P12
PB11: CN5.36 R106.2 U4.R13
PB12: CN5.41 R109.2 SB51.2 U4.L13
PB13: CN5.43 R115.2 R259.2 U4.K14
PB14: CN5.35 D6.D3 R288.2 U4.R14
PB15: CN5.38 D6.C3 R286.2 U4.R15
PC0: CN5.11 R125.2 U4.M2
PC1: CN5.16 SB22.1 SB31.1 U4.M3
PC2: CN5.23 R241.1 SB38.1 U4.M4
PC3: CN5.27 SB41.1 SB44.1 U4.L4
PC4: CN5.25 SB40.1 SB43.1 U4.N5
PC5: CN5.46 SB53.1 SB55.1 U4.P5
PC13: CN6.6 R180.2 R216.2 U4.D1
PC14: R18.2 SB25.1 U4.E1
PC15: R17.2 SB26.1 U4.F1
PD4: CN11.28 U4.D11 U9.G2 U14.A2
PD5: CN11.26 R107.2 U4.C10
PD7: CN11.24 R91.2 U4.A11
PE0: CN11.25 U4.A6 U13.K9 U14.A1
PE1: CN11.23 U4.A5 U13.K1 U14.B2
PF6: CN5.7 R24.2 R237.2
PF7: CN5.8 R22.2 R228.1
PF8: CN5.17 R41.2 R238.1
PF9: CN5.12 R26.2 R227.2
PF10: CN5.9 JP24.2 R302.2 U4.L1
PF11: CN10.8 R51.2 U13.J9
PG6: CN5.51 SB11.1 U4.J15
PG7: CN5.47 SB10.1 U4.J14
PG8: CN10.40 R61.2 U13.J1
PG9: CN6.17 R193.2 U4.D9
PG10: CN11.27 R147.2 U4.C8
PG11: CN6.33 R252.1 SB46.1 U4.B8
PG12: CN6.15 R215.1 U4.C7
PG13: CN6.25 R243.1 U4.B3
PG14: CN6.29 R244.1 U4.A4
PG15: CN11.19 R44.2 U13.K7
PH0: R19.1 SB27.1 U4.G1
PH1: C23.1 SB28.1 U4.H1 X1.1
PH2: CN11.2 R287.2 U4.K4
PH3: CN10.1 R251.1 U13.J8
PH4: CN5.28 R123.2 U4.H4
PH5: CN10.2 R254.1 U13.K8
PH6: CN5.37 SB42.1 SB45.1 U4.P13
PH7: CN5.40 R45.2 U4.N13
PI4: CN11.17 U4.C3 U13.F8
PI5: CN11.15 U4.D3 U13.F2
PI8: CN6.9 R295.1 U4.C2
PI11: CN5.2 R124.2 U4.F3
PI12: CN6.7 CN20.26 U4.E3
PI13: CN6.2 CN20.28 U4.G3
PI14: CN5.32 CN20.32 R225.1
PK7: CN6.8 R192.2 U4.C4
PWR_ENN: R159.2 U17.3 U21.28
RESET#: B1.2 B1.3 C99.2 CN20.36 D2.1 D16.2 R104.2 R127.2 R224.1 U4.J1 U6.29 U21.18
STL_USB_DM: R166.2 U21.32
STL_USB_DP: R169.2 U21.33
STLINK_RX: CN23.1 JP20.3 U21.13
STLINK_TX: CN23.2 JP14.3 U21.12
STM_JTCK_SWCLK: CN18.3 U21.37
STM_JTMS_SWDIO: CN18.1 U21.34
STM_RST: C175.2 R297.1 SB64.2 U21.7
SWIM_PU_CTRL: U21.4
T_JTDO: JP4.1 R99.2 U21.16 U21.31
U5V_ST_LINK: C55.2 JP13.11 SB19.2 U17.6 U17.7
USB_RENUMN: R294.2 U21.38
VREF+: C105.1 C110.2 R33.2 TP6.1 U4.P1
VUSB_ST_LINK: C59.1 CN21.1 D12.1 R156.1 R159.1 R200.1 R293.2 SB19.1 U17.1 U17.2

Pads without a net: CN2 2 6 8; CN7 1 4 7 9; CN9 7; CN12 7; CN16 11 12 13 14; CN18 5; CN19 5; CN20 24 41 42 44 46 48; CN22 1 4 8; CN24 6; CN25 5 7; CN26 5 7; CN27 6; D5 A2 B1 B2 C2; D6 A2 B1 B2 C2; U1 2; U3 3 4 5 6 11 12 13 14; U5 4 8 9 11 12 14 15 18 19 21; U6 8 9 10 11 12; U9 A1 A8 B1 C1 D1 E1 F8 G1 G8 H1 H8; U12 3; U13 E3 E7 H3 H7 K2 K3; U14 E3; U20 5; U21 11 14 40 41 42 43 45 46; U22 3 4 5 6 25 38 41; U23 A6 A8 B1 B4 B5 B7 B8 B9 C3 C4 C5 C7 C8 E1 E5 F4 F5 F6 F8 F9 G4 H2 H3 H4 H5

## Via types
v1: diameter 0.508, hole 0.254, TOP to BOTTOM, 660 vias
v2: diameter 0.305, hole 0.152, TOP to BOTTOM, 13 vias
v3: diameter 0.61, hole 0.305, TOP to BOTTOM, 598 vias
v4: diameter 0.483, hole 0.254, TOP to BOTTOM, 41 vias
v5: diameter 0.406, hole 0.203, TOP to BOTTOM, 295 vias

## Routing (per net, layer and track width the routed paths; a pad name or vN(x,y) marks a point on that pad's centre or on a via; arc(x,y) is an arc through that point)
+1V8: length 49.5
  TOP w0.229: 117.98,26.81 117.98,26.96 U23.D1 ; U23.D8 v2(118.11,30.83)
  TOP w0.254: 117.98,26.81 117.98,26.19 v3(118.24,25.94) ; U23.G9 119.36,31.34 119.13,31.57 119.13,32 120.27,33.15 120.27,33.78 C68.1
  TOP w0.508: CN4.1 149.28,156.72 148.54,156.72 148.16,157.1 v3(147.7,157.1) ; U19.2 110.57,46.46 ; U19.2 109.86,45.35 ; U19.2 109.86,47.56 ; U19.2 109.14,46.46 ; 115.57,41.07 C61.1 ; C61.1 114.6,41.91 ; C61.1 116.54,41.91 ; C61.1 115.57,42.75 ; C68.1 v3(120.9,33.4) ; U19.4 109.86,41.26 ; U19.4 111.71,40.16 ; U19.4 108,40.16 ; U19.4 109.86,39.05 ; v3(151.26,157.23) 151.79,156.69 CN4.2 ; C66.1 118.11,33.66 v3(117.86,33.4) ; X3.4 139.04,149.17 137.45,147.57 R25.2 136.37,147.57 TP1.1 ; C86.1 v3(118.24,25.94)
  BOTTOM w0.508: v3(146.91,146.38) 147.12,146.18 R235.2 ; C102.1 152.53,157.84 ; C102.1 151.88,157.23 ; C102.1 152.53,156.62 ; C103.2 148.59,157.84 ; C103.2 148.59,156.62 ; C103.2 147.94,157.23 ; v3(146.74,149.22) R231.2 ; 144.98,150.37 135.61,150.37 TP1.1
  vias: v3(116.19,39.33) v3(116.19,38.44) v3(117.2,39.33) v3(117.2,38.44) v3(118.22,39.33) v3(118.22,38.44) v3(136.78,100.33) v3(137.67,100.33)
+2V8: length 31.2
  TOP w0.508: 132.84,151.7 U2.4 ; U2.4 130.99,152.81 ; U2.4 134.7,152.81 ; U2.4 132.84,153.91 ; 132.13,159.11 U2.2 ; U2.2 133.55,159.11 ; U2.2 132.84,160.21 ; U2.2 132.84,158 ; CN4.40 151.18,137.69 150.93,137.95 v3(150.93,137.95) ; 138.48,153.8 C19.1 ; C19.1 139.32,154.76 ; C19.1 140.16,153.8 ; C19.1 139.32,152.83 ; CN4.39 150.17,137.69 v3(150.55,137.31) ; R15.1 138.91,156.08 ; R15.1 138.3,155.49 ; R15.1 137.69,156.08 ; TP5.1 131.32,155.65
  BOTTOM w0.508: R230.2 R234.2 v3(153.92,149.1) ; v3(151,156.46) 150.33,155.79 T4.1 150.45,155.76 T5.1 ; v3(150.55,137.31) 149.94,137.92 C120.1 ; C119.1 150.95,137.92 v3(150.93,137.95)
  vias: v3(138.56,152.27) v3(138.56,151.51) v3(139.32,152.27) v3(139.32,151.51) v3(140.08,152.27) v3(140.08,151.51)
+3V3: length 240.6
  TOP w0.229: U23.B2 116.86,27.58 v2(117.11,27.83) 117.36,27.58 U23.C2 ; v2(118.11,27.33) 118.11,27.34 U23.D2
  TOP w0.254: U8.25 30.2,109.19 v3(30.48,109.47) ; C29.1 124.33,127.38 124.84,127.38 125.27,126.96 U6.48 ; 118.41,32.05 118.36,32 U23.E9 ; v3(30.73,102.69) 30.2,103.23 U8.16 ; U6.22 129.77,116.11 C37.2 ; U6.32 134.12,122.54 C33.2 ; v3(24.77,105.16) 24.9,105.29 U8.6 ; U8.30 27.7,109.08 v3(27.43,109.35) 27.2,109.11 U8.31
  TOP w0.279: U22.24 59.52,36.41 60.01,36.9 v3(60.17,36.9) ; v3(52.07,30.61) 52.07,30.44 51.73,30.1 U22.1 ; U22.48 50.67,30.9 50.97,30.61 v3(51.31,30.61) ; v3(51.73,36.62) U22.36
  TOP w0.305: v3(33.48,129.77) 33.76,129.77 33.85,129.87 U5.22 ; U5.26 v3(33.15,132.47)
  TOP w0.381: U13.N9 v5(86.66,75.14) ; v5(95.07,74.93) 95.06,74.94 U13.C9 ; U13.M9 v5(87.46,75.14) ; v5(92.67,74.93) 92.66,74.94 U13.F9 ; U9.D8 78.91,99.19 v5(79.38,98.73) ; v5(88.64,82.6) 88.66,82.58 U13.L1 ; U13.D9 94.26,74.94 v5(94.27,74.93) ; v5(77.09,107.19) 76.91,107.01 U9.F1 ; U13.E1 v5(93.86,82.34) ; U13.L7 v5(88.26,76.74) ; U14.E1 65.66,80.11 v5(65.66,80.64) ; U9.G5 v4(76.38,101.9) ; v5(85.06,76.74) 85.06,76.8 85.4,77.14 U13.R7 ; U13.P2 v5(85.86,81.54) ; U13.B2 v5(96.26,81.54) ; U14.A6 v5(69.04,75.98) ; U13.P7 v5(85.86,76.74) ; U13.B7 v5(96.26,76.74) ; U14.D6 66.42,76.36 v5(66.79,75.98) ; v5(97.06,76.74) U13.A7
  TOP w0.508: R77.2 v3(137.79,117.22) ; R2.1 v3(141.99,168.78) ; v3(119.51,111.38) 118.8,111.38 118.03,110.62 CN12.1 ; R134.1 v3(13.97,89.79) ; R212.1 v3(73.53,16.51) ; R213.1 v3(76.33,16.51) ; R76.2 v3(137.79,118.62) ; 55.3,55.5 C56.1 ; C56.1 56.26,54.66 ; C56.1 57.23,55.5 ; B2.1 v3(54.74,4.38) ; CN16.4 v3(140.24,47.47) ; v3(131.27,116.36) 131.27,115.9 130.68,115.32 C37.2 ; R176.2 v3(46.86,28.57) ; CN11.40 104.57,93.27 v3(103.63,92.33) ; R141.2 v3(146.69,80.52) ; v3(122.45,128.96) 123.01,128.96 C29.1 ; R118.2 v3(13.97,102.62) ; C57.1 59.16,55.88 ; C57.1 58.55,55.23 ; C57.1 57.94,55.88 ; v3(74.57,109.58) 74.04,110.11 R90.2 ; R122.1 v3(24.13,98.3) ; R210.1 v3(67.94,16.51) ; R81.2 R82.2 v3(129.29,112.52) ; U19.3 108.27,46.46 ; U19.3 106.84,46.46 ; U19.3 107.56,45.35 ; U19.3 107.56,47.56 ; v3(92.32,133.73) 92.08,133.73 91.95,133.86 C26.1 ; R170.1 v3(136.59,33.02) ; v3(130.81,37.34) 130.81,37.44 130.78,37.47 U20.3 ; R97.1 v3(135,109.09) ; R137.2 v3(145.8,88.27) ; R128.1 19.24,98.87 T1.2 v3(19.24,101.41) ; R143.2 v3(143.38,73.41) ; v3(21.21,9.91) LD3.1 ; R13.2 v3(105.66,157.48) ; B2.4 v3(63.44,4.38) ; R85.1 85.85,113.03 85.5,113.39 v3(85.5,113.87) ; R160.1 v3(136.53,46.74) ; v3(90.04,101.47) 89.28,102.23 R116.2 ; v3(147.07,150.62) 145.8,151.89 145.8,159.26 v3(147.83,161.29) ; C85.1 116.84,24.64 v3(116.59,24.89) ; R188.2 v3(125.09,24.89) ; R144.2 v3(143.38,72.01) ; R146.2 v3(68.96,67.94) ; R214.1 v3(79.12,16.51) ; CN28.3 97.03,10.29 C96.2 v3(98.17,13.97) ; 118.41,32.05 118.41,32.41 118.87,32.87 118.87,33.78 C67.1 119.51,34.54 119.63,34.67 v3(119.63,33.4) ; R20.2 v3(86.11,151.64) ; R191.1 v3(72.39,23.5) ; C84.1 v3(115.44,24.89) ; R186.1 v3(37.85,24.64) ; R136.2 v3(144.4,88.27) ; v3(132.84,166.75) C1.1 133.9,168.69 U1.7 ; v3(137.41,107.77) C45.2 141.1,106.68 141.6,106.17 ; C28.1 v3(61.34,128.27) ; C46.2 v3(138.43,104.9) ; R75.2 v3(137.79,120.02) ; L6.1 53.21,24.77 v3(53.21,25.15) R182.2 ; CN2.5 v3(37.72,161.29) ; U3.2 v3(33.78,145.16) ; R135.2 v3(13.97,87.88) ; R161.1 v3(136.53,45.21) ; CN6.48 v3(113.53,126.75) ; v3(136.27,165.61) 135.51,165.61 C3.1 135.51,164.59 v3(136.27,164.59) ; CN20.50 v3(63.18,25.15) ; R1.1 v3(134.37,166.62) ; R155.2 v3(136.53,53.85) ; R133.2 v3(8.89,88.9) ; v3(114.05,24.89) C83.1 ; R120.1 v3(135,101.47) ; R211.1 v3(70.74,16.51) ; R168.2 v3(139.95,34.54) ; v3(19.18,9.91) LD4.1 ; R114.1 v3(135,103.12) ; R190.1 v3(67.82,23.24) ; LD1.1 v3(25.27,9.91) ; R162.1 v3(136.53,43.69) ; R165.1 v3(48.39,38.99) ; LD2.1 v3(23.24,9.91) ; R194.1 v3(122.43,21.46) ; R79.2 v3(137.67,115.82) ; R89.1 v3(135,110.74) ; R74.1 v3(122.43,120.02) ; R92.2 v3(80.26,110.62) ; v3(151.89,115.44) 151.89,116.46 R78.2 ; CN5.48 v3(44.7,126.75) ; R96.2 v3(9.91,109.22) ; C33.2 v3(136.02,122.17) ; RV1.1 C90.1 ; R157.1 v3(136.53,52.32) ; R158.1 v3(136.53,50.8) ; R218.1 v3(60.81,11.05) ; R131.2 v3(153.16,95.99)
  TOP w1.27: U18.2 U18.4
  BOTTOM w0.381: C160.1 66.42,75.61 v5(66.79,75.98) ; C156.1 95.63,77.37 v5(96.26,76.74) ; C152.1 88.64,83.32 v5(88.64,82.6) ; v5(79.38,98.73) C149.1 ; v5(87.46,75.14) 87.88,74.72 C164.1 ; C165.1 86.61,75.1 v5(86.66,75.14) ; v5(96.26,81.54) 96.14,81.66 C150.1 ; v4(76.38,101.9) 76.17,102.11 C148.1 ; C158.1 86.49,77.37 v5(85.86,76.74) ; v5(95.07,74.93) 95.07,74.6 96.14,73.53 C161.1 ; v5(88.26,76.74) 88.52,77 C157.1 ; C155.1 97.03,76.77 v5(97.06,76.74) ; C159.1 68.96,75.9 v5(69.04,75.98) ; C163.1 92.67,73.49 v5(92.67,74.93) ; v5(65.66,80.64) 65.66,80.77 C154.1 ; C153.1 86.49,82.17 v5(85.86,81.54) ; v5(94.27,74.93) 94.27,73.57 C162.1 ; v5(77.09,107.19) 76.45,106.55 C145.1 ; v5(93.86,82.34) 93.6,82.6 C151.1
  BOTTOM w0.508: v3(33.15,132.47) 33.02,132.59 C135.1 ; C127.1 v3(55.88,137.41) ; C143.1 v3(30.48,109.47) ; C173.2 v3(51.31,30.61) ; R226.1 34.04,152.53 33.78,152.27 v3(33.66,152.27) ; R229.1 v3(147.07,150.62) ; C107.1 v3(33.78,145.16) ; v3(16,111.89) R282.2 ; R20.2 v3(86.11,151.64) ; C146.1 25.4,105.79 v3(24.77,105.16) ; C168.2 51.82,36.7 v3(51.73,36.62) ; v3(27.43,109.35) 27.18,109.09 C144.1 ; v3(52.07,30.61) C176.2 ; C147.1 30.73,103.5 v3(30.73,102.69) ; v3(60.17,36.9) 60.02,36.9 59.57,36.45 C170.1 C171.2 ; C166.1 v3(130.81,37.34) ; R285.2 v3(75.82,95.38)
  vias: v1(59.82,55.75) v1(59.82,55.12) v1(59.82,54.48) v1(60.58,55.75) v1(60.58,55.12) v1(60.58,54.48) v3(43.05,44.96) v3(43.18,47.5) v3(43.31,54.86) v3(43.31,50.8) v3(55.24,52.96) v3(55.24,47.62) v3(55.24,44.58) v3(106.93,48.01) v3(107.95,48.01)
+3V3_ST_LINK: length 22.8
  TOP w0.279: U21.24 40.85,36.41 v3(41.15,36.7) ; U21.1 32.94,28.87 32.74,28.68 v1(32.16,28.68) ; U21.36 32.94,38.95 32.66,39.22 v3(32.66,39.27) ; v1(30.1,30.48) 30.52,30.9 U21.48 ; v1(37.08,28.07) 36.94,28.21 U21.9
  TOP w0.508: T3.3 v3(19.96,30.9) ; U16.5 22.11,71.25 C51.2 C53.1 v3(21.84,69.85) ; R203.2 v3(18.92,15.49) ; JP15.1 v3(30.23,17.65)
  BOTTOM w0.508: v3(32.66,39.27) 32.77,39.17 C167.2 ; v1(37.08,28.07) 38.1,29.08 C174.2 ; C169.2 v3(41.15,36.7) ; C172.2 v1(30.1,30.48) ; R289.1 38.35,34.92 v3(37.59,35.69) ; v3(34.2,28.16) 34.04,28.32 R297.2
+5V: length 239.9
  TOP w0.508: JP13.12 7.11,63.58 ; JP13.12 8.08,62.61 ; JP13.12 7.11,61.65 ; 7.11,69.27 JP13.6 ; JP13.6 6.15,70.23 ; JP13.6 7.11,71.2 ; JP13.6 8.08,70.23 ; 46.61,56.93 U18.3 ; U18.3 47.5,58.85 ; U18.3 45.72,58.85 ; U18.3 46.61,60.77 ; JP13.2 7.11,76.28 ; JP13.2 8.08,75.31 ; JP13.2 6.15,75.31 ; JP13.2 7.11,74.35 ; 7.11,65.15 8.08,65.15 ; 7.11,65.15 7.11,64.19 ; 7.11,65.15 7.11,66.12 ; U11.5 9.72,96.2 v3(9.02,96.9) ; 45.79,65.02 C54.1 ; C54.1 47.35,64.24 ; C54.1 47.35,65.81 ; JP13.8 8.08,67.69 ; JP13.8 7.11,66.73 ; JP13.8 7.11,68.66 ; JP13.8 6.15,67.69 ; R142.2 v3(12.95,76.33) ; JP13.4 8.08,72.77 ; JP13.4 7.11,73.74 ; JP13.4 6.15,72.77 ; JP13.4 7.11,71.81 ; 130.54,158 U2.3 ; U2.3 129.83,159.11 ; U2.3 130.54,160.21 ; TP14.1 12.7,65.99 ; TP14.1 11.73,65.02 ; TP14.1 12.7,64.06 ; TP14.1 13.67,65.02 ; v3(40.26,28.45) 40.77,27.94 42.29,27.94 44.45,25.78 44.45,19.94 41.66,17.14 D15.1 ; 128.8,159.94 124.87,159.94 121.23,156.31 121.23,143.23 118.87,140.87 118.87,120.73 117.27,119.13 CN6.60 ; CN5.60 46.82,116.93 45.97,116.08 41.15,116.08 36.58,120.65 24.89,120.65 21.41,117.17 21.41,114.88 21.02,114.49 v3(20.7,114.49) U7.5
  TOP w0.762: L5.1 65.53,63.37 59.18,69.72 50.16,69.72 47.75,67.31
  L4_SIG w0.508: 7.11,71.81 JP13.4 ; JP13.4 7.11,73.74 ; JP13.4 6.15,72.77 ; JP13.4 8.08,72.77 ; v3(40.26,28.45) 38.38,30.33 34.9,30.33 29.97,35.26 29.97,61.24 27.08,64.14 27.05,64.14 v3(26.92,64.26) ; JP13.2 7.11,76.28 ; JP13.2 8.08,75.31 ; JP13.2 6.15,75.31 ; JP13.2 7.11,74.35 ; 71.78,167.64 CN1.25 ; CN1.25 72.74,168.61 ; CN1.25 73.71,167.64
  vias: v3(13.18,93.75) v3(13.18,92.91) v3(20.73,115.27) v3(129.06,161.9) v3(129.82,161.9)
D5V: length 22.1
  TOP w0.508: v1(15.11,86.23) 16.26,85.09 D7.1
  TOP w0.762: 39.34,125.48 CN5.49 43.51,125.48 ; CN6.49 v1(108.08,125.48)
  L4_SIG w0.508: JP13.7 4.57,68.66 ; JP13.7 4.57,66.73 ; JP13.7 5.54,67.69 ; JP13.7 3.61,67.69
  vias: v1(14.91,96.04) v1(15.57,96.06) v1(29.21,123.19) v1(30.23,123.19) v1(44.3,121.34) v1(44.83,120.98) v1(107.31,125.48)
GND: length 656.5
  TOP w0.203: D3.B1 8.56,116.13 v3(8.76,116.33) 8.56,116.53 D3.B2 ; D4.B1 8.56,114.48 v3(8.76,114.68) 8.56,114.88 D4.B2
  TOP w0.229: v3(116.96,26.41) 116.96,26.48 117.36,26.88 U23.C1 ; U23.A3 115.7,28.08 v3(115.7,28.08) 115.7,28.32 115.96,28.58 U23.A4 ; v2(118.11,27.83) 118.36,27.58 U23.E2 ; U23.D6 v2(117.61,29.83) ; v2(119.61,29.33) 119.61,29.33 119.36,29.09 U23.G5 ; U23.E7 118.36,30.08 v2(118.11,30.33) U23.E8 ; U23.A5 116.11,29.34 v3(115.7,29.34) ; U23.A1 116.33,27.08 115.82,26.58 v3(115.7,26.58) ; v2(119.11,29.83) U23.F7
  TOP w0.254: v3(8,97.28) D5.D2 ; U6.15 126.27,116.36 126.87,115.75 v3(126.87,115.32) ; U8.1 25.5,107.8 v3(25.15,107.44) 25.29,107.29 U8.2 ; v3(120.26,31.76) 120.26,31.74 120.02,31.5 120.02,31.24 U23.H9 ; U6.19 128.27,118.49 v3(128.52,118.75) ; D6.D2 v3(8,82.93) ; U6.36 133.22,124.54 v3(133.48,124.28) 133.24,124.04 U6.35 ; v3(127.15,124.84) 126.36,124.84 125.77,125.44 U6.47
  TOP w0.279: U21.23 38.95,35.9 v3(38.86,35.81) ; v3(33.99,39.27) 33.96,39.24 33.91,39.24 33.44,38.77 U21.35 ; U21.47 v3(30.1,31.41) ; U22.8 v3(55.23,30.47) ; v3(52.2,39.37) 52.23,39.33 U22.35 ; U22.47 v3(51.31,31.41) ; U21.8 36.44,28.31 v3(36.21,28.08) ; v3(56.87,36.07) 57.03,35.9 U22.23
  TOP w0.305: U24.5 122.96,14.5 v3(122.56,14.1) ; v3(33.15,130.94) 33.57,130.52 U5.23 ; R140.1 145.29,81.41 U12.2
  TOP w0.356: U5.25 37.12,131.82 v3(37.64,132.33)
  TOP w0.381: v5(79.5,136.91) 79.59,136.91 U4.F9 ; v5(79.61,135.29) U4.G10 ; v3(127.05,100.84) 126.92,100.71 U10.2 ; U4.K9 v5(77.22,136.89) 76.82,137.29 U4.K8 ; v5(79.61,139.29) U4.G6 ; U13.F1 v5(93.06,82.34) ; U14.D1 v5(66.41,80.64) ; U14.E6 v5(65.29,75.98) ; U4.H10 v5(78.01,135.29) ; CN14.5 v3(2.95,86.64) ; U13.P8 v5(85.86,75.94) ; v5(77.21,135.29) 77.61,135.69 U4.J10 ; U13.L9 v5(88.26,75.14) ; U13.D1 v5(94.66,82.34) ; U9.H2 74.22,105.37 v5(74.17,105.42) ; v5(74.01,143.29) U4.N1 ; U4.F8 v5(80.41,136.89) ; U4.F6 v5(80.41,139.29) ; v5(78.26,98.78) 77.91,99.13 U9.E8 ; v5(79.61,138.49) U4.F7 ; U13.B8 v5(96.26,75.94) ; U13.M1 87.86,82.58 v5(87.84,82.6) ; U13.A3 v5(97.06,80.74) ; U13.N1 87.06,82.58 v5(87.04,82.6) ; U4.J6 77.2,138.48 v5(77.19,138.48) ; U4.F10 v5(80.41,135.29) ; v5(74.3,100.22) 74.45,100.37 U9.H7 ; U4.K10 v5(76.41,135.29) ; v3(145.16,78.23) 145.29,78.11 U15.2 ; v5(76.41,139.29) U4.K6 ; U13.P3 v5(85.86,80.74) ; U13.E9 93.46,74.94 v5(93.47,74.93) ; U4.H6 v5(78.01,138.49) ; v3(5.59,101.35) 5.24,100.99 CN13.5 ; U4.M1 v5(74.81,143.29) ; U13.B3 v5(96.26,80.74) ; U4.K7 v5(76.41,138.49) ; U4.L6 v5(75.61,139.29) ; U13.C1 v5(95.46,82.34) ; v5(80.41,142.49) U4.F2 ; U13.L3 v5(88.26,80.74) ; U13.R3 v5(85.06,80.74) ; U25.5 v3(2.31,8.28)
  TOP w0.508: v3(118.97,102.16) 118.54,101.73 CN12.15 ; C65.2 v3(116.71,37.08) ; C92.1 v3(69.34,16.51) ; C41.2 v3(24.77,112.01) ; C41.2 24.12,110.74 ; C41.2 24.77,110.13 ; U25.2 4.02,8.88 v3(4.62,9.47) ; CN4.7 149.28,153.67 v3(147.7,153.67) ; R149.1 v3(143.64,62.48) ; R23.1 v3(92.58,149.86) ; C29.2 123.42,130.07 v3(122.45,130.07) ; v3(73.43,29.01) 73.43,28.85 73.34,28.77 CN20.34 ; CN4.37 150.02,138.69 150.27,138.94 v3(150.52,138.94) ; R36.1 v3(95.89,143.38) ; L4.1 v3(62.38,40.39) ; C47.2 v3(31.88,97.28) ; v3(131.57,163.32) 131.57,162.56 C5.2 132.72,162.43 v3(132.72,163.32) ; CN5.39 39.59,131.83 v3(39.45,131.97) ; C79.1 v3(54.99,26.04) ; CN4.22 154.3,146.69 154.69,146.3 v3(154.94,146.3) ; C11.2 76.71,160.53 76.2,161.04 v3(75.96,161.04) ; 24.26,53.01 C58.2 ; C58.2 24.26,56.46 ; C58.2 27,54.74 ; CN5.59 42.67,119.13 43.43,118.36 v3(43.81,118.36) ; D14.3 v3(138.56,17.65) ; 114.6,44.7 C61.2 ; C61.2 116.54,44.7 ; C61.2 115.57,45.54 ; R223.1 v3(143.13,4.45) ; R187.1 39.98,25.65 ; R187.1 v3(39.37,24.77) ; R187.1 38.76,25.65 ; C81.2 v3(36.32,24.77) ; 57.94,57.4 C57.2 ; C57.2 58.55,58.05 ; C57.2 59.16,57.4 ; v3(32.64,57.53) 33.15,57.53 C55.1 33.27,58.42 v3(32.66,58.42) ; B1.4 v3(49.91,4.38) ; C35.2 v3(5.08,120.78) ; CN6.1 111.38,155.96 v3(111.89,156.46) ; C86.2 v3(118.24,21.34) ; C9.1 v3(62.48,157.73) ; v3(138.37,6.21) CN26.3 v3(140.76,4.08) ; C44.2 v3(5.08,105.41) ; U1.8 v3(132.95,168.76) ; CN13.10 v3(3.02,99.69) ; CN16.9 v3(140.52,53.02) ; CN4.16 153.5,149.69 v3(153.8,149.99) ; C31.1 134.54,125.04 v3(134.54,125.17) 134.54,125.27 C30.2 ; C96.1 v3(98.04,15.49) ; R148.1 v3(143.51,65.53) ; 51.69,56.93 U18.1 ; U18.1 52.58,58.85 ; U18.1 50.8,58.85 ; U18.1 51.69,60.77 ; CN10.30 v3(54.81,99.62) ; R6.2 v3(138.3,161.8) ; R83.1 v3(132.08,112.52) ; R219.1 v3(105.66,8.38) ; v3(113.39,150.7) 113.56,150.88 CN6.10 ; C83.2 v3(114.05,21.34) ; C12.1 80.98,160.27 v3(80.24,159.54) ; U17.4 v3(37.49,52.2) ; CN20.1 v3(93.66,33.34) ; CN6.50 v3(113.53,125.48) ; CN6.39 v3(112.01,131.83) ; CN4.3 v3(147.83,155.69) ; C20.2 v3(73.91,151.64) ; v3(61.37,157.67) 61.37,158.47 C8.1 ; CN10.10 v3(54.74,112.32) ; B1.1 v3(40.96,4.38) ; C27.1 v3(25.02,129.29) ; C56.2 56.26,59.13 ; C56.2 56.26,57.45 ; C56.2 55.3,58.29 ; C56.2 57.23,58.29 ; R129.1 v3(10.67,98.81) ; C39.2 v3(30.86,113.28) ; C39.2 31.51,112.27 ; C39.2 30.86,111.66 ; R21.2 88.49,150.62 ; R21.2 87.88,151.22 ; R21.2 87.27,150.62 ; R40.1 95.77,139.32 v3(96.02,139.06) ; v3(43.31,156.72) 42.55,155.96 CN5.1 ; CN12.3 118.11,109.35 118.52,108.94 118.59,108.94 119,108.53 v3(119,108.48) 119,108.33 118.75,108.08 CN12.5 ; R38.1 v3(96.01,142.11) ; R80.1 v3(13.72,114.81) ; CN12.19 117.86,99.19 v3(118.87,98.17) ; R172.2 R175.2 46.61,30.99 v3(46.23,31.37) ; R221.2 v3(115.95,10.67) ; U20.2 130.78,38.73 130.81,38.76 v3(130.81,38.86) ; v3(84.56,114.48) 84.33,114.25 C40.2 ; CN12.9 v3(119,105.54) ; C84.2 v3(115.44,21.35) ; R173.1 v3(26.67,31.75) ; R173.1 27.69,32.36 ; R173.1 27.69,31.14 ; C73.2 v3(126.29,31.5) ; R208.2 v3(38.48,12.83) ; CN4.11 150.11,151.69 150.3,151.51 v3(151,151.51) ; C69.2 v3(122.3,37.08) ; C34.2 v3(3.56,120.78) ; C87.2 v3(121.03,21.34) ; C2.2 v3(138.94,166.37) ; CN6.30 v3(113.53,138.18) ; C99.1 v3(49.66,12.19) ; C13.1 v3(84.2,161.42) ; C14.1 v3(87,161.42) ; CN5.50 v3(44.83,125.48) ; C17.2 67.31,157.73 v3(67.06,157.48) ; 112.15,45.35 U19.1 ; U19.1 112.15,47.56 ; U19.1 112.87,46.46 ; 25.64,112.27 C38.2 ; C38.2 26.29,111.66 ; C38.2 v3(26.29,113.41) ; C4.2 v3(140.59,163.83) ; B3.5 v3(77.22,11.18) ; C22.2 82.85,148.51 v3(82.55,148.21) ; 31.9,25.65 R185.1 ; R185.1 33.12,25.65 ; R185.1 v3(32.51,24.77) ; X3.2 v3(144.15,143.23) ; B3.10 77.73,5.96 v3(78.36,5.33) ; C68.2 v3(120.9,37.08) ; C52.1 v3(29.97,70.48) ; v3(19.68,107.95) 19.05,108.58 R94.1 ; R163.2 v3(138.94,41.02) ; R222.2 v3(117.47,10.67) ; CN11.9 v3(102.31,112.32) ; v3(112.01,118.36) 111.99,118.36 111.23,119.13 CN6.59 ; C93.1 v3(72.14,16.51) ; C85.2 v3(116.84,21.34) ; CN12.13 v3(119,103) ; v3(32.94,76.15) BT1.2 v3(32.94,80.49) ; C21.2 81.58,148.26 v3(81.53,148.21) ; C101.2 v3(8,6.22) ; C72.1 v3(110.62,32) ; CN12.11 v3(119,104.27) ; v3(69.47,10.41) 70.1,9.78 B3.9 ; C32.2 84.77,123.83 v3(84.9,123.7) ; C80.2 v3(34.04,24.77) ; CN5.19 v3(43.56,144.53) ; C91.1 v3(66.42,16.51) ; U11.2 v3(10.67,94.49) ; R139.1 v3(13.97,81.28) ; B3.8 v3(77.34,4.45) ; R197.2 v3(117.73,16.26) ; U1.5 135.8,168.9 136.02,168.68 v3(136.02,168.66) ; C90.2 v3(36.07,15.49) ; R217.2 v3(58.93,9.91) ; C42.2 v3(32.38,111.89) ; U7.2 v3(18.31,113.54) ; R32.1 v3(96.01,145.92) ; C89.2 v3(128.4,14.1) ; LD12.1 v3(15,7.5) ; C18.1 C7.1 v3(74.42,161.04) ; R153.1 v3(39.01,55.63) ; C37.1 v3(130.68,112.52) ; C63.1 v3(113.92,37.08) ; LD10.2 v3(13.97,79.25) ; 51.45,64.24 C54.2 ; C54.2 51.45,65.81 ; C54.2 53.02,65.02 ; R181.1 v3(49.78,25.4) ; R145.1 v3(143.38,70.48) ; C48.2 v3(4.45,92.58) ; C36.2 v3(19.68,117.73) ; CN14.10 v3(3.02,85.34) ; CN11.30 v3(103.38,99.62) ; 30.63,25.65 R184.1 ; R184.1 31.85,25.65 ; R184.1 v3(31.24,24.77) ; U3.10 v3(24,151.51) ; R105.1 v3(11.43,106.68) ; C97.2 v3(100.2,15.49) ; CN20.30 v3(75.88,29.08) ; C23.2 75.44,148.46 v3(75.69,148.21) ; v3(130.81,165.61) 131.7,165.61 C3.2 131.7,164.59 v3(130.81,164.59) ; C19.2 142.11,154.76 ; C19.2 141.27,153.8 ; C19.2 142.11,152.83 ; C19.2 142.95,153.8 ; C51.1 v3(18.41,71.25) ; CN4.12 154.45,151.69 154.69,151.46 v3(154.69,151.26) ; C15.2 v3(91.31,161.29) ; v3(119.25,101.09) 119.18,101.02 118.67,101.02 118.11,100.46 CN12.17 ; CN16.6 v3(140.32,49.67) ; v3(147.57,147.07) 147.66,147.07 147.67,147.06 147.96,147.06 148.33,146.69 CN4.21 ; U16.2 v3(26.42,71.5) ; CN6.19 v3(112.14,144.53) ; C74.1 v3(110.62,30.61) ; CN10.9 v3(53.29,112.32) ; v3(155.32,153.69) CN4.8 ; v3(60.33,23.62) 59.69,23.62 C82.2 59.44,24.64 v3(60.33,24.64) ; C49.1 v3(18.41,72.64) ; C45.1 v3(134.87,106.68) ; C78.1 v3(57.02,26.29) ; C50.1 v3(29.97,72.39) ; B3.7 v3(70.61,11.18) ; C43.2 v3(3.56,105.41) ; CN4.38 151.78,138.69 150.9,139.57 v3(150.9,139.62) ; CN10.29 v3(53.54,99.62) ; v3(32.64,46.1) 32.51,46.1 31.75,46.86 C59.2 31.75,47.52 32.66,48.44 v3(32.69,48.44) ; R179.2 v3(129.29,27.43) ; C75.2 v3(126.31,30.23) ; C1.2 v3(131.32,168.66) ; CN5.30 v3(44.83,138.18) ; CN11.10 v3(103.38,112.32) ; v3(68.71,155.19) 68.58,155.32 68.58,158.5 C10.1 ; R178.2 v3(129.29,28.83) ; C53.2 v3(18.41,69.85) ; C46.1 v3(134.75,104.9) ; C66.2 v3(118.11,37.08) ; C67.2 v3(119.51,37.08) ; R98.1 v3(22.61,109.47) ; v3(17.78,104.9) 17.65,104.78 R110.1 ; T2.2 v3(12.83,82.87) ; CN2.7 v3(37.85,158.75) ; v3(155.32,155.69) CN4.4 ; L1.1 v3(6.6,120.78) ; C94.1 v3(74.93,16.51) ; R12.2 v3(89.92,161.29) ; v3(143.38,80.52) R140.1 ; C33.1 v3(137.79,121.41) ; C24.1 v3(19.68,148.46) ; CN20.19 v3(82.23,33.4) ; CN11.29 v3(101.98,99.62) ; C6.1 v3(67.31,161.28) ; C95.1 v3(77.72,16.51) ; CN20.20 v3(82.23,29.08) ; CN20.37 v3(70.8,33.46) ; CN5.10 v3(44.7,150.88) ; CN20.2 v3(93.66,24.83) ; C16.1 v3(104.27,157.61) ; R174.1 v3(136.59,31.5)
  L4_SIG w0.508: 98.12,9.65 CN28.2 ; CN28.2 99.75,9.65 ; CN28.2 98.93,8.84 ; CN28.2 98.93,10.47 ; CN21.5 9.41,29.62 ; CN21.5 7.62,27.83 ; CN21.5 7.62,31.41 ; CN21.5 5.83,29.62 ; CN14.6 4.46,83.81 ; CN14.6 3.46,83.07 ; CN14.6 4.46,82.33 ; RV1.3 32.79,8.13 ; RV1.3 32,8.92 ; RV1.3 31.22,8.13 ; RV1.3 32,7.34 ; 151.82,67.94 CN15.16 ; CN15.16 152.78,66.98 ; CN15.16 152.78,68.91 ; CN15.16 153.75,67.94 ; CN15.20 153.75,62.87 ; CN15.20 151.82,62.87 ; CN15.20 152.78,61.9 ; CN15.20 152.78,63.83 ; 2.44,81.19 CN14.9 1.28,80.29 ; JP16.1 48.51,18.75 ; JP16.1 49.48,17.78 ; JP16.1 47.55,17.78 ; JP16.1 48.51,16.81 ; CN21.4 11.13,22.23 ; CN21.4 10.29,21.39 ; CN21.4 10.29,23.06 ; CN21.4 9.45,22.23 ; 89.41,3.35 TP16.1 ; TP16.1 90.37,4.32 ; TP16.1 89.41,5.28 ; TP16.1 88.44,4.32 ; 140.69,111.25 141.6,111.25 ; 141.6,111.25 142.52,111.25 ; 141.6,111.25 141.6,112.17 ; 141.6,111.25 141.6,110.34 ; 152.78,77.14 CN15.8 ; CN15.8 151.82,78.11 ; CN15.8 153.75,78.11 ; CN15.8 152.78,79.07 ; 6.35,3.89 CN27.5 ; CN27.5 7.26,4.81 ; CN27.5 5.44,4.81 ; CN27.5 6.35,5.72 ; CN15.18 153.75,65.41 ; CN15.18 152.78,66.37 ; CN15.18 152.78,64.44 ; CN15.18 151.82,65.41 ; CN15.6 153.75,80.64 ; CN15.6 152.78,79.68 ; CN15.6 152.78,81.61 ; CN15.6 151.82,80.64 ; 152.78,72.06 CN15.12 ; CN15.12 151.82,73.03 ; CN15.12 153.75,73.03 ; CN15.12 152.78,73.99 ; 147.37,14.63 CN22.6 ; CN22.6 149.81,14.63 ; CN22.6 148.59,13.54 ; CN22.6 148.59,15.72 ; 6.6,51.51 L3.4 ; L3.4 7.8,52.7 ; L3.4 6.6,53.9 ; L3.4 5.41,52.7 ; 1.28,90.4 CN14.8 2.44,89.49 ; 3.46,101.97 CN13.7 ; CN13.7 5.46,101.97 ; CN13.7 4.46,101.23 ; CN13.7 4.46,102.71 ; 4.46,86.88 CN14.7 ; CN14.7 4.46,88.36 ; CN14.7 3.46,87.62 ; 147.44,113.28 CN9.13 ; CN9.13 146.05,114.68 ; CN9.13 148.84,114.68 ; CN15.10 153.75,75.56 ; CN15.10 152.78,74.6 ; CN15.10 151.82,75.56 ; CN15.10 152.78,76.53 ; L3.6 10.3,55.21 ; L3.6 9.1,54.01 ; L3.6 7.91,55.21 ; L3.6 9.1,56.4 ; 7.62,15.63 CN21.6 ; CN21.6 5.83,17.42 ; CN21.6 7.62,19.22 ; CN21.6 9.41,17.42 ; CN13.6 5.46,97.42 ; CN13.6 3.46,97.42 ; CN13.6 4.46,96.68 ; CN13.6 4.46,98.16 ; 27.48,39.12 CN18.2 ; CN18.2 28.45,40.08 ; CN18.2 28.45,38.15 ; 151.82,70.48 CN15.14 ; CN15.14 152.78,71.45 ; CN15.14 153.75,70.48 ; CN15.14 152.78,69.52 ; CN19.2 46.1,40.08 ; CN19.2 45.14,39.12 ; CN19.2 47.07,39.12 ; CN19.2 46.1,38.15 ; 1.28,94.64 CN13.9 2.44,95.54 ; CN22.11 148.54,6.27 ; CN22.11 147.19,3.78 ; CN22.11 147.19,8.76 ; CN22.11 145.85,6.27 ; CN24.2 124.71,12.84 ; CN24.2 124.71,11.01 ; CN24.2 125.63,11.92 ; CN24.2 123.8,11.92 ; CN15.4 153.75,83.19 ; CN15.4 152.78,82.22 ; CN15.4 151.82,83.19 ; CN15.4 152.78,84.15 ; 147.19,28.83 CN22.10 ; CN22.10 145.85,31.32 ; CN22.10 147.19,33.81 ; CN22.10 148.54,31.32 ; L3.5 2.8,52.7 ; L3.5 1.6,51.51 ; L3.5 1.6,53.9 ; 33.93,91.11 TP13.1 ; TP13.1 34.9,92.08 ; TP13.1 33.93,93.04 ; TP13.1 32.97,92.08 ; CN22.3 145.8,19.89 ; CN22.3 144.58,18.8 ; CN22.3 145.8,17.7 ; CN22.3 147.02,18.8 ; 146.05,98.93 CN9.14 ; CN9.14 147.44,97.53 ; CN9.14 147.44,100.33 ; CN9.14 148.84,98.93 ; 6.35,10.78 CN27.2 ; CN27.2 7.26,11.7 ; CN27.2 6.35,12.61 ; CN27.2 5.44,11.7 ; 2.44,103.85 CN13.8 1.28,104.75
  BOTTOM w0.102: 85.09,141.48 C116.2
  BOTTOM w0.381: v5(74.01,136.89) 74.3,137.17 C125.2 ; v5(79.61,138.49) 79.76,138.34 C123.2 ; v5(82.81,138.49) 82.93,138.37 C122.2 84.2,137.79 ; v5(77.21,135.29) 77.47,135.55 C129.2 ; v5(77.98,141.68) 78.05,141.6 78.74,141.6 ; 78.74,133.22 78.74,131.22 v5(78.87,131.09) ; C157.2 88.52,80.48 v5(88.26,80.74) ; v5(96.26,80.74) 95.63,80.11 C156.2 ; C158.2 86.49,80.11 v5(85.86,80.74) ; v5(74.3,100.22) 75.2,100.22 C148.2 ; C110.1 74.68,143.42 v5(74.81,143.29) ; C124.2 77.47,138.2 v5(77.19,138.48) ; C155.2 97.03,80.71 v5(97.06,80.74) ; v5(71.43,134.75) 71.43,135.43 C132.2 ; v5(79.5,136.91) 79.76,136.65 C128.2 ; C118.2 78.75,138.43 v5(79.61,139.29) ; v5(70.64,141.38) 70.74,141.48 C113.1 ; C145.2 74.68,105.88 74.22,105.42 v5(74.17,105.42) ; C126.2 71.62,138.05 71.37,138.3 v5(71.37,138.33) 71.37,138.73 C117.2 ; 84.2,136.14 84.2,136 v5(85.27,134.93) ; C159.2 68.1,73.28 v3(67.82,73.56) ; C131.2 v5(78.74,137.16)
  BOTTOM w0.508: v3(58.67,142.37) 58.67,143.26 C112.2 57.78,143.13 v3(57.78,142.37) ; C151.2 v3(92.58,85.22) ; C140.2 v3(130.3,120.27) ; T7.2 13.65,105.09 v3(13.84,105.28) ; C166.2 v3(130.81,38.86) ; C119.2 151.71,139.62 v3(150.9,139.62) ; C162.2 v3(95,71.88) ; v3(27.05,104.65) 26.67,104.27 C146.2 ; v3(87.38,85.34) 87.25,85.22 C153.2 ; T6.2 11.56,109.5 v3(11.56,108.97) ; v3(29.84,106.05) 30.73,105.16 C147.2 ; C144.2 25.65,107.95 v3(25.15,107.44) ; v3(150.52,138.94) 150.37,139.09 149.71,139.09 C120.2 ; v3(28.45,107.44) 28.96,107.95 C143.2 ; v3(63.25,142.44) 63.25,143.13 C111.2 64.26,143.13 v3(64.26,142.44) ; C134.1 33.27,131.06 v3(33.15,130.94) 33.02,131.06 C135.2 ; v3(63.25,145.03) 63.25,145.8 C105.2 64.14,145.92 v3(64.14,145.03) ; v3(38.86,35.81) 38.48,36.2 C169.1 ; C115.2 v3(58.93,139.95) ; C152.2 v3(89.28,85.22) ; v3(78.99,124.08) 78.87,124.08 77.98,123.19 C138.2 ; v3(67.21,74.07) C160.2 ; C149.2 v3(79.38,95.25) ; v3(88.95,72.14) 88.7,71.88 C164.2 C165.2 ; v3(51.31,31.41) 51.02,31.41 50.8,31.62 50.16,31.62 ; v3(57.78,147.83) 57.78,146.81 C106.2 58.67,146.69 v3(58.67,147.83) ; v3(36.21,28.08) 36.21,28.46 36.83,29.08 C175.1 SB64.1 ; v3(79.48,145.03) 79.5,145.03 79.12,144.65 C109.2 ; v3(83.57,144.4) 83.31,144.15 C108.2 ; v3(18.16,30.73) 18.41,30.99 R296.1 ; C103.1 v3(150.11,158.12) ; C174.1 v3(38.1,31.62) 38.48,32 R292.1 ; v3(52.2,39.37) 51.82,38.99 C168.1 ; C141.1 v3(127.38,120.14) ; v3(33.99,39.27) 34.04,39.22 34.04,39.12 34.29,38.86 C167.1 ; v5(85.72,142.09) 85.36,141.73 85.34,141.73 85.09,141.48 ; v3(64.77,137.29) 65.66,137.29 R249.1 ; C172.1 30.7,32 v3(30.1,31.41) ; 34.8,146.18 v3(33.78,146.18) ; C171.1 C170.2 57.25,36.45 v3(56.87,36.07) ; C102.2 v3(155.19,157.23) ; C176.1 v3(53.09,28.19) ; C163.2 v3(92.58,70.87) ; C161.2 v3(96.14,70.87) ; C150.2 v3(95,85.22) ; C142.2 v3(23.11,112.39) ; C137.1 128.78,125.09 v3(128.91,124.97) 128.91,123.95 C139.2 ; C154.2 v3(65.41,82.93)
  vias: v1(23.62,58.29) v1(23.62,57.4) v1(24.38,58.29) v1(24.38,57.4) v1(25.15,58.29) v1(25.15,57.4) v1(59.82,58.93) v1(59.82,58.17) v1(59.82,57.4) v1(60.58,58.93) v1(60.58,58.17) v1(60.58,57.4) v1(124.79,16.48) v1(124.76,14.02) v1(134.11,105.41) v3(1.27,47.75) v3(1.4,32.64) v3(1.4,21.34) v3(2.16,1.52) v3(4.67,6.93) v3(6.45,8.08) v3(24.13,103.63) v3(25.02,61.98) v3(27.05,107.44) v3(27.05,106.05) v3(28.45,106.05) v3(28.45,104.65) v3(28.7,1.52) v3(29.84,107.44) v3(29.84,104.65) v3(30.1,92.08) v3(30.3,82.14) v3(31.78,20.37) v3(34.52,96.95) v3(37.97,20.4) v3(38.73,101.19) v3(44.63,139.29) v3(51.05,1.52) v3(52.98,137.64) v3(55.32,138.46) v3(59.05,135.08) v3(65.79,1.4) v3(70.23,154.31) v3(71.96,65.96) v3(74.68,155.83) v3(74.68,154.31) v3(77.34,151.89) v3(79.22,48.74) v3(79.76,1.27) v3(81.2,65.94) v3(82.04,35.69) v3(83.67,53.52) v3(84.07,156.08) v3(87.88,152.53) v3(88.01,45.21) v3(90.93,156.72) v3(92.05,65.81) v3(93.6,23.62) v3(93.85,1.02) v3(98.04,41.4) v3(99.31,53.34) v3(104.9,1.14) v3(105.16,59.31) v3(110.62,34.29) v3(111.25,65.66) v3(117.73,46.48) v3(117.73,45.59) v3(117.73,44.7) v3(118.49,46.48) v3(118.49,45.59) v3(118.49,44.7) v3(125.09,42.55) v3(125.35,60.83) v3(125.48,81.28) v3(126.47,15.21) v3(131.06,30.61) v3(132.21,20.19) v3(136.65,69.34) v3(140.21,85.98) v3(140.46,99.95) v3(141.6,152.15) v3(141.6,151.38) v3(142.24,120.78) v3(142.37,130.68) v3(142.49,152.15) v3(142.49,151.41) v3(142.88,126.42) v3(143.26,89.92) v3(143.38,152.15) v3(143.38,151.41) v3(155.07,51.82) v3(155.45,74.3) v3(155.57,107.44) v3(155.57,92.46) v3(155.7,33.02) v3(155.7,18.16) v3(155.7,6.22) v3(155.83,117.22)
